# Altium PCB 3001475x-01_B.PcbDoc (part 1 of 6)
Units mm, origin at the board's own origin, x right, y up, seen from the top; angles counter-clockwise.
Board outline 335 x 91 mm, 12 copper layers (Top Layer, L2 GND, Layer 3, L4 GND, Layer 5, L6 PWR, L7 3V3, Layer 8, L9 GND, Layer 10, L11 GND, Bottom Layer), stack 1.59 mm thick; 339 components, 431 nets, 1732 pads, 1526 vias.
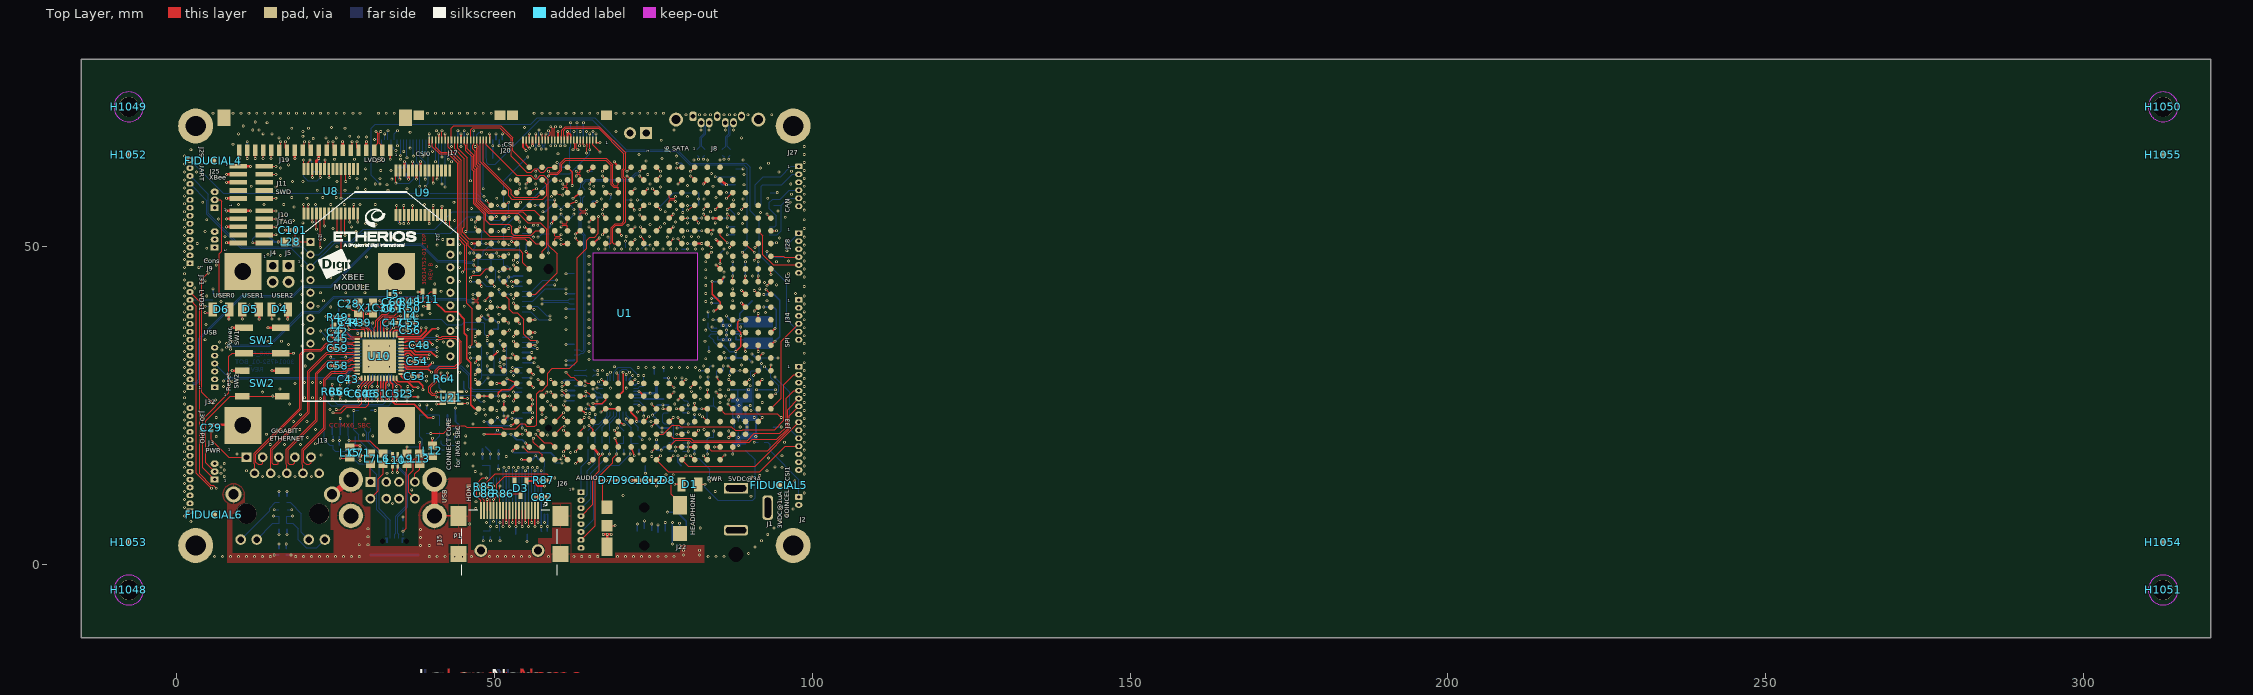
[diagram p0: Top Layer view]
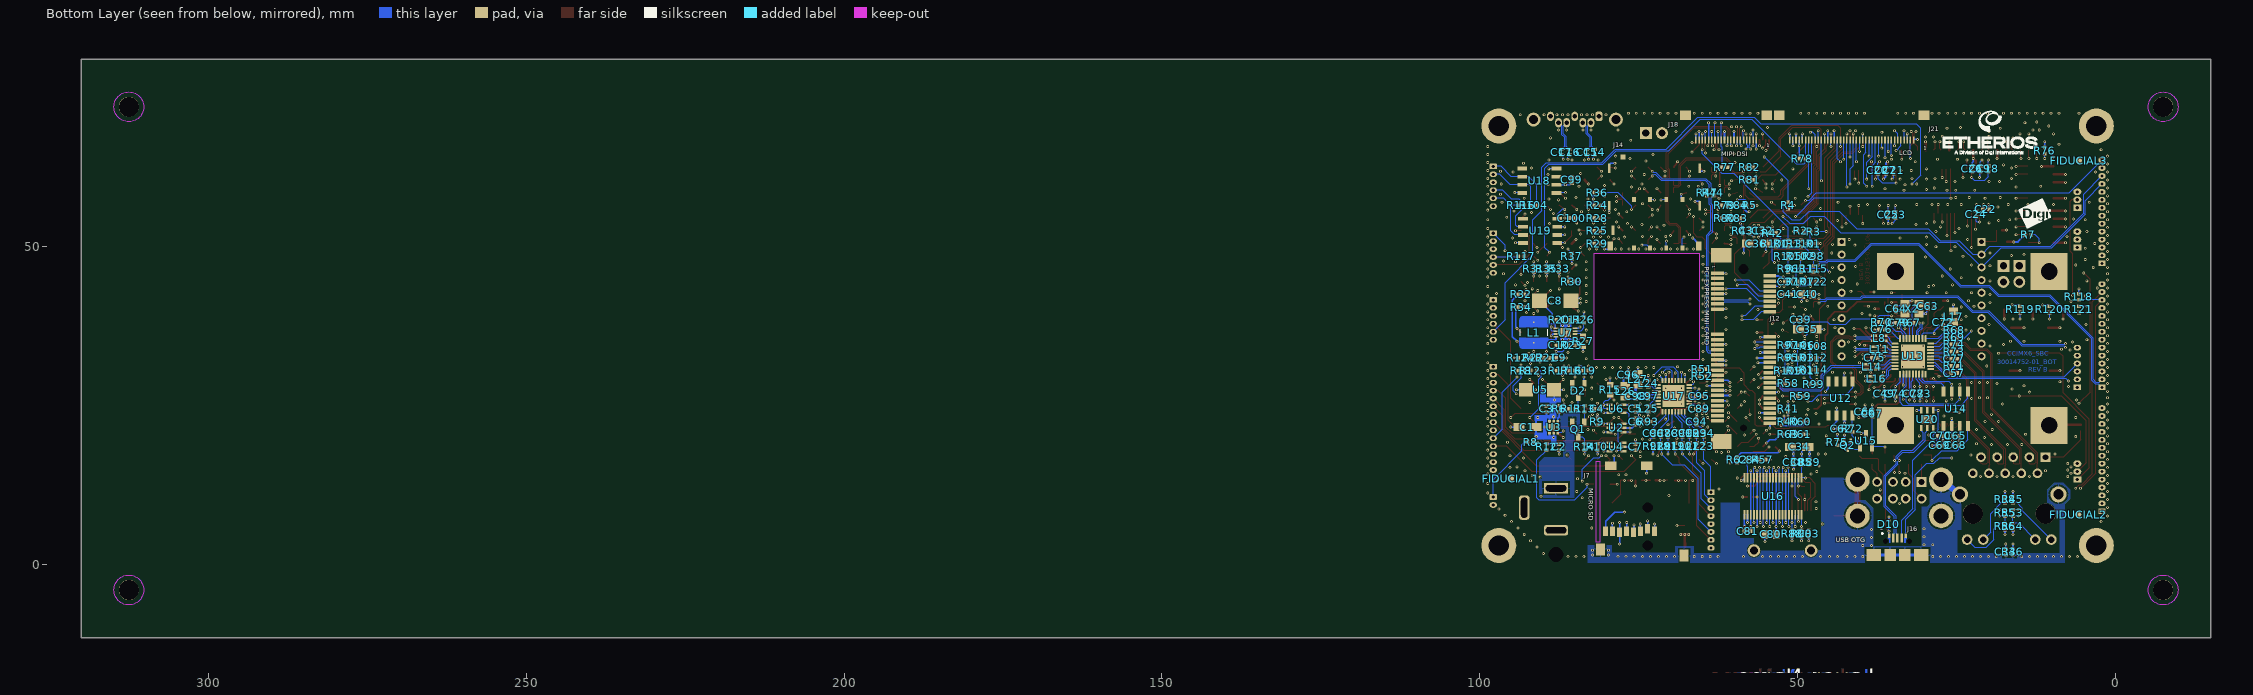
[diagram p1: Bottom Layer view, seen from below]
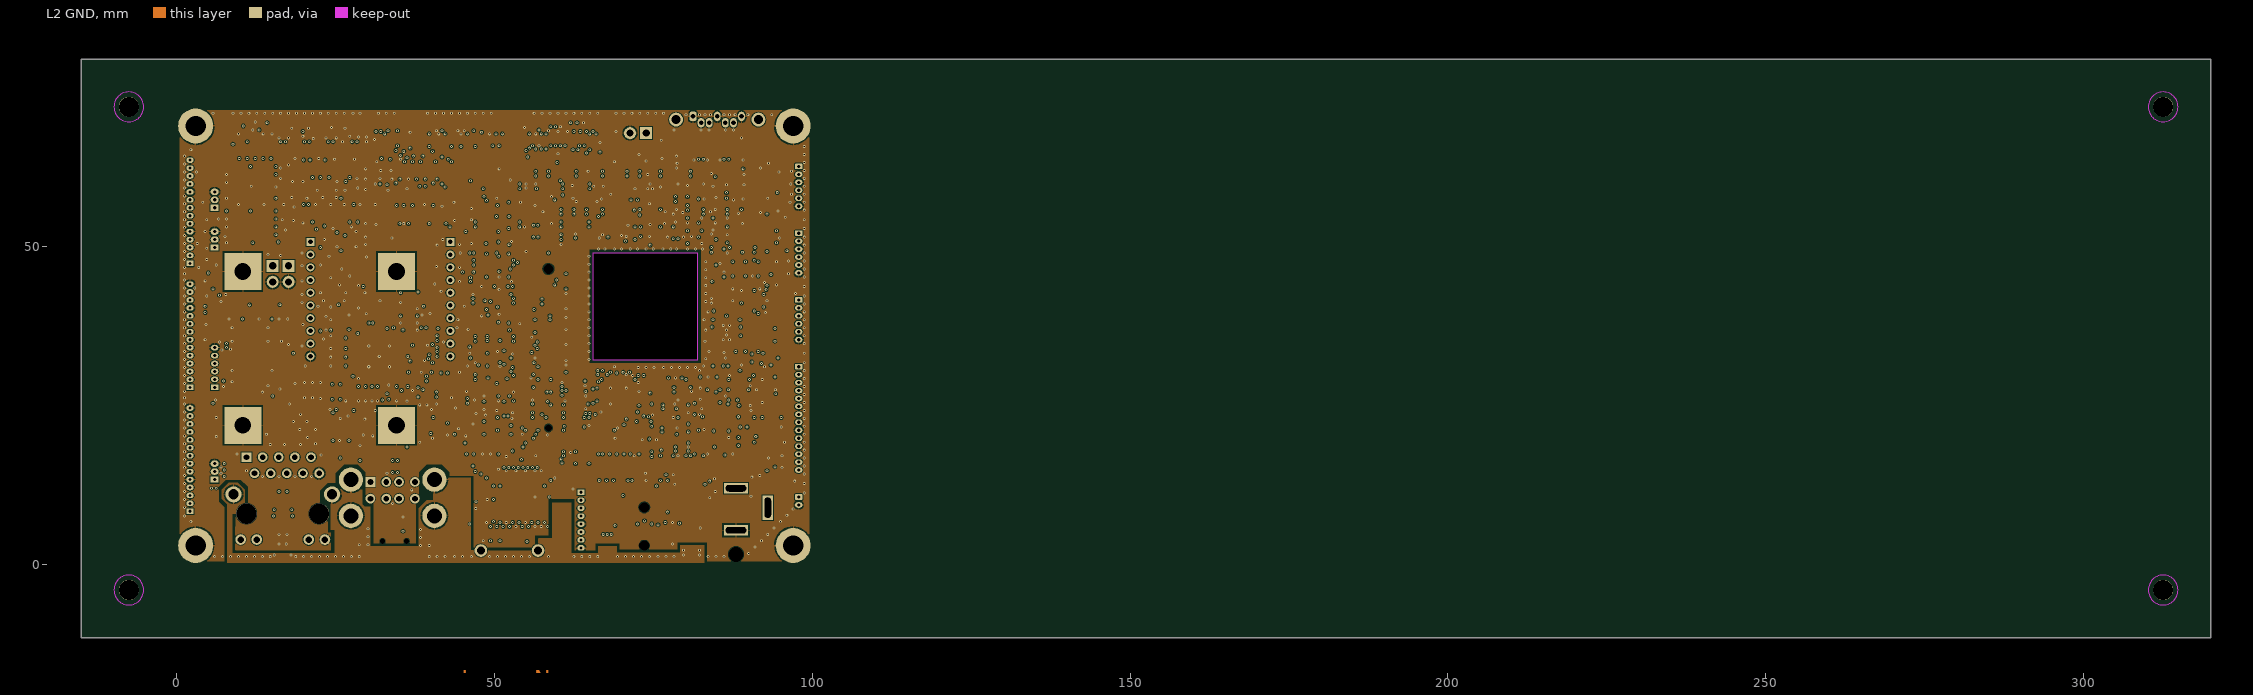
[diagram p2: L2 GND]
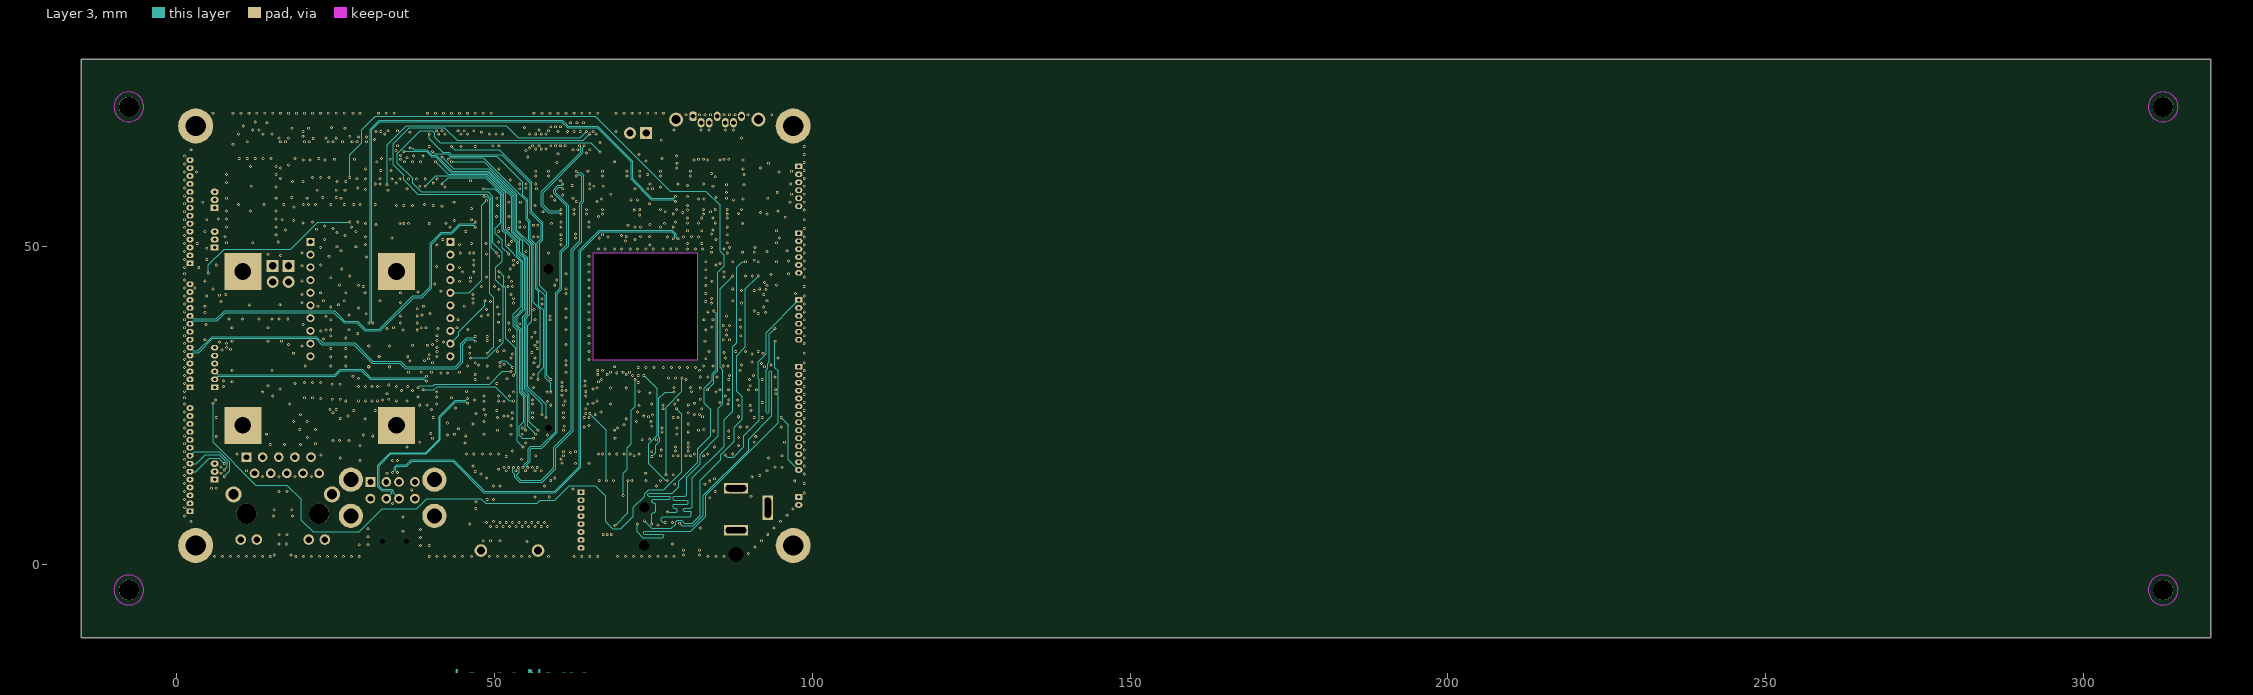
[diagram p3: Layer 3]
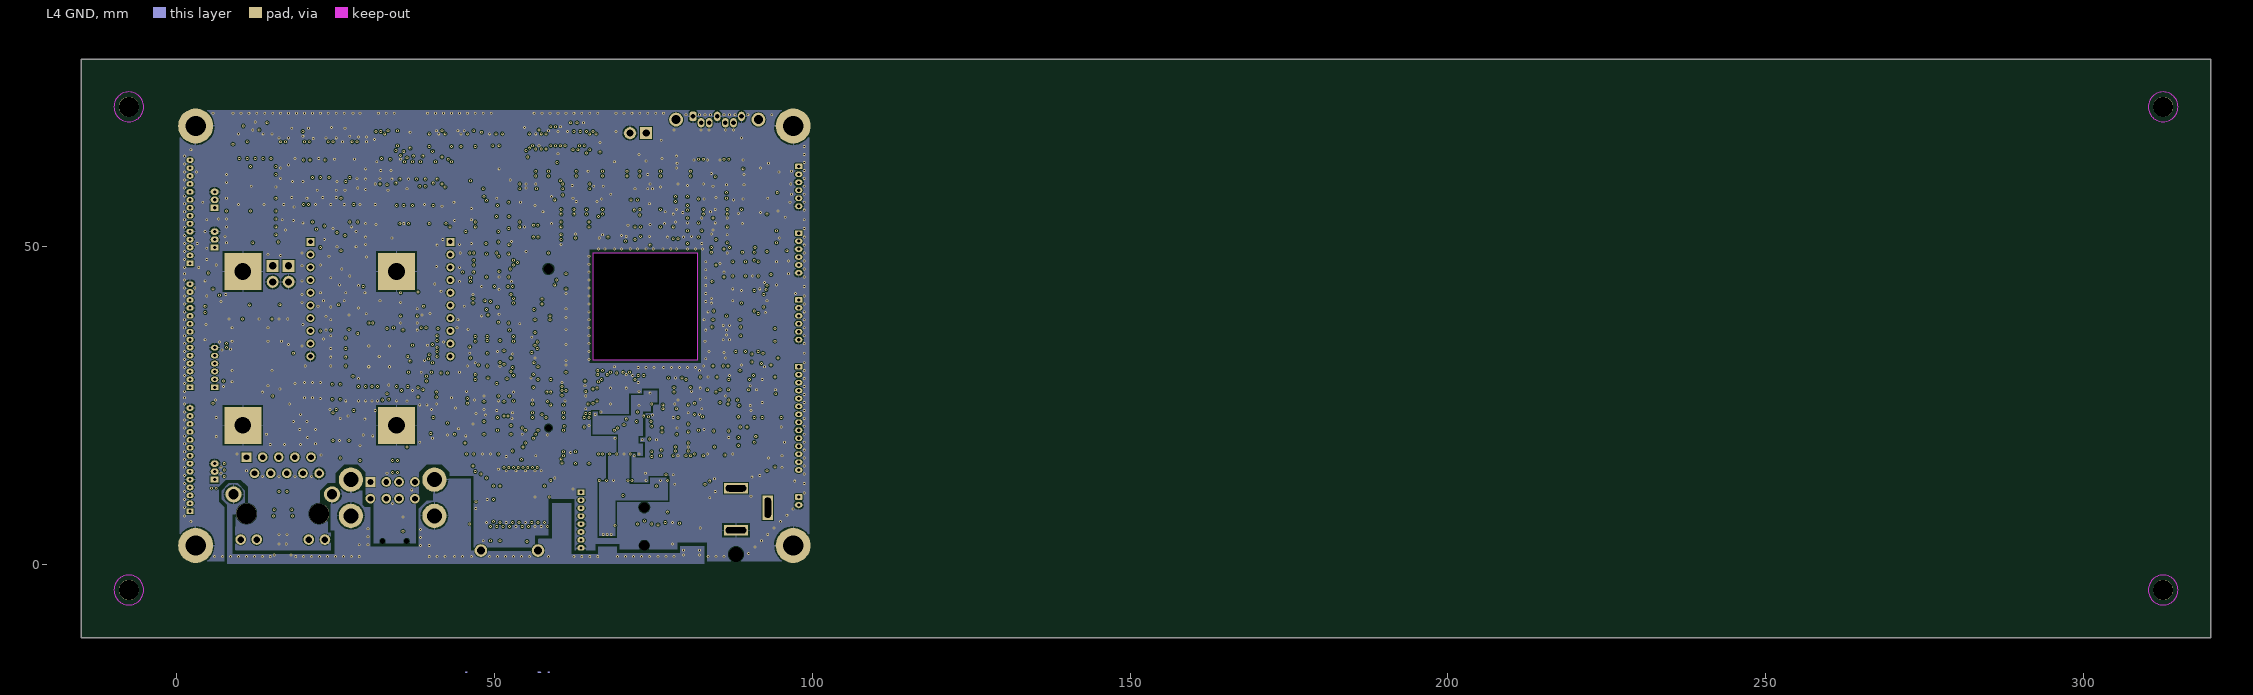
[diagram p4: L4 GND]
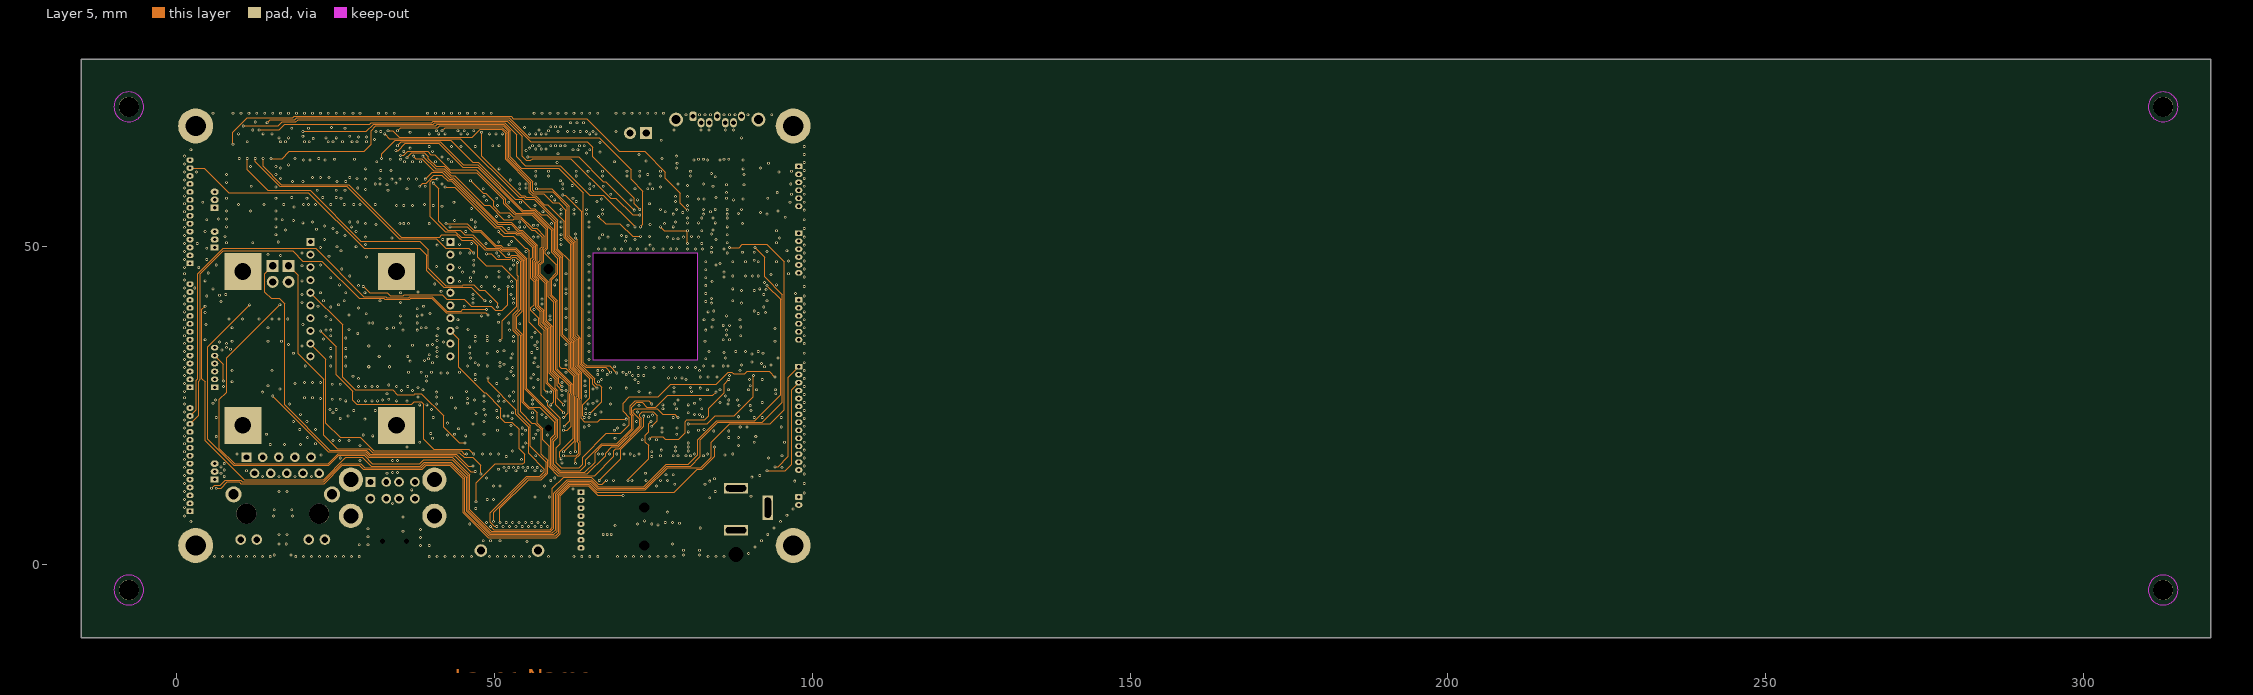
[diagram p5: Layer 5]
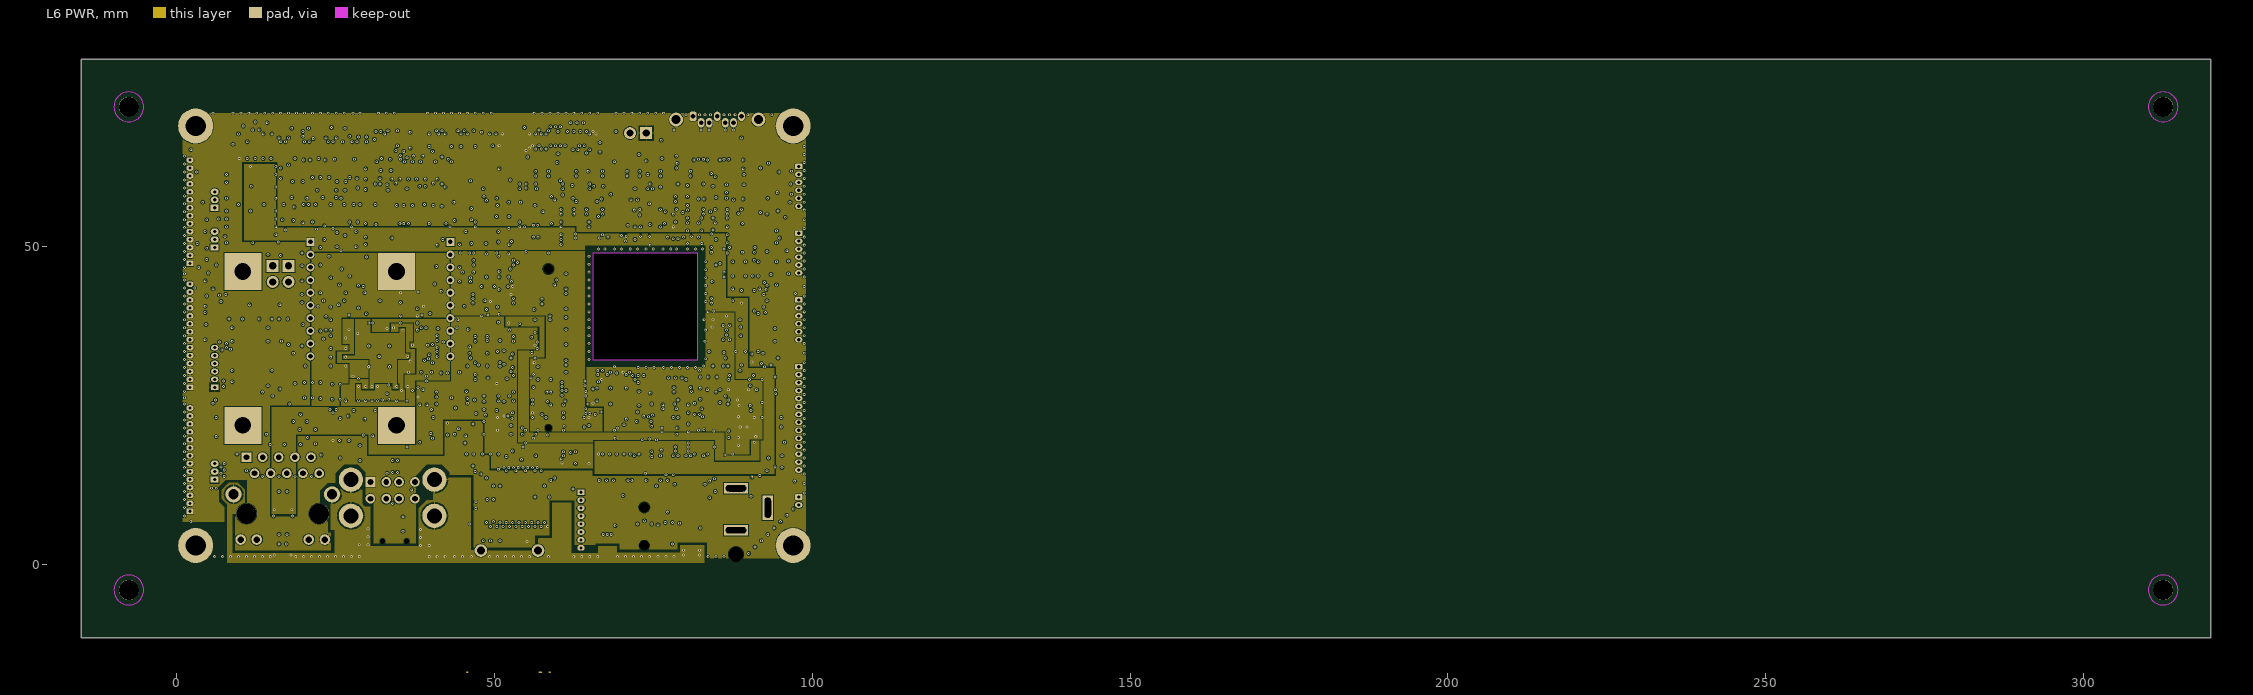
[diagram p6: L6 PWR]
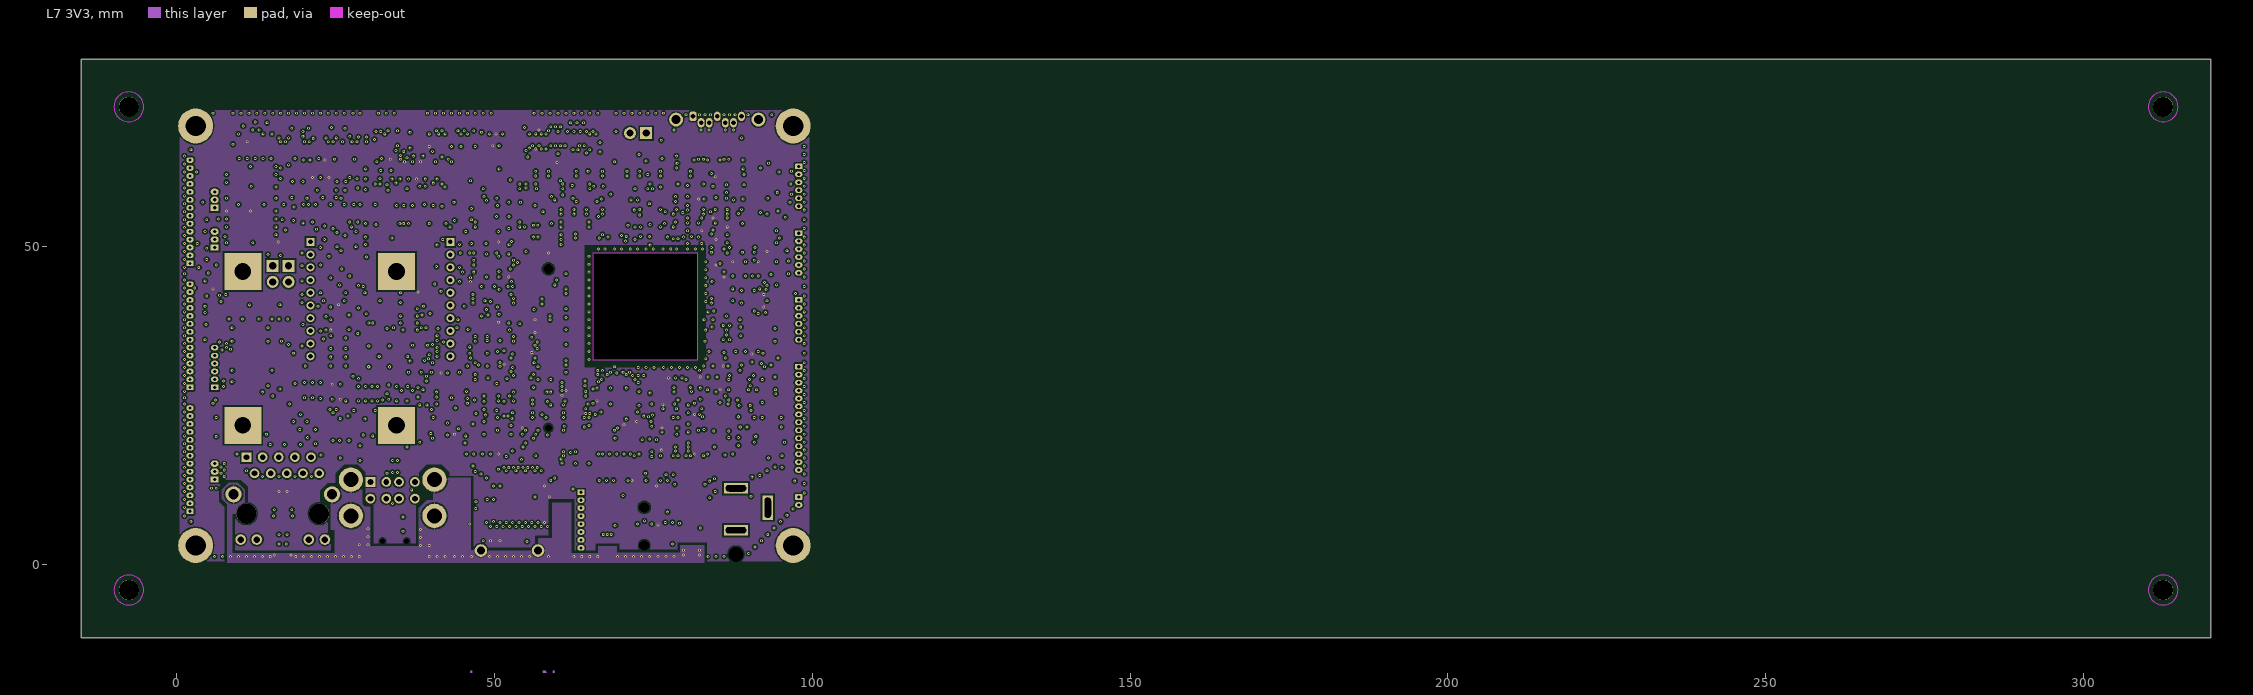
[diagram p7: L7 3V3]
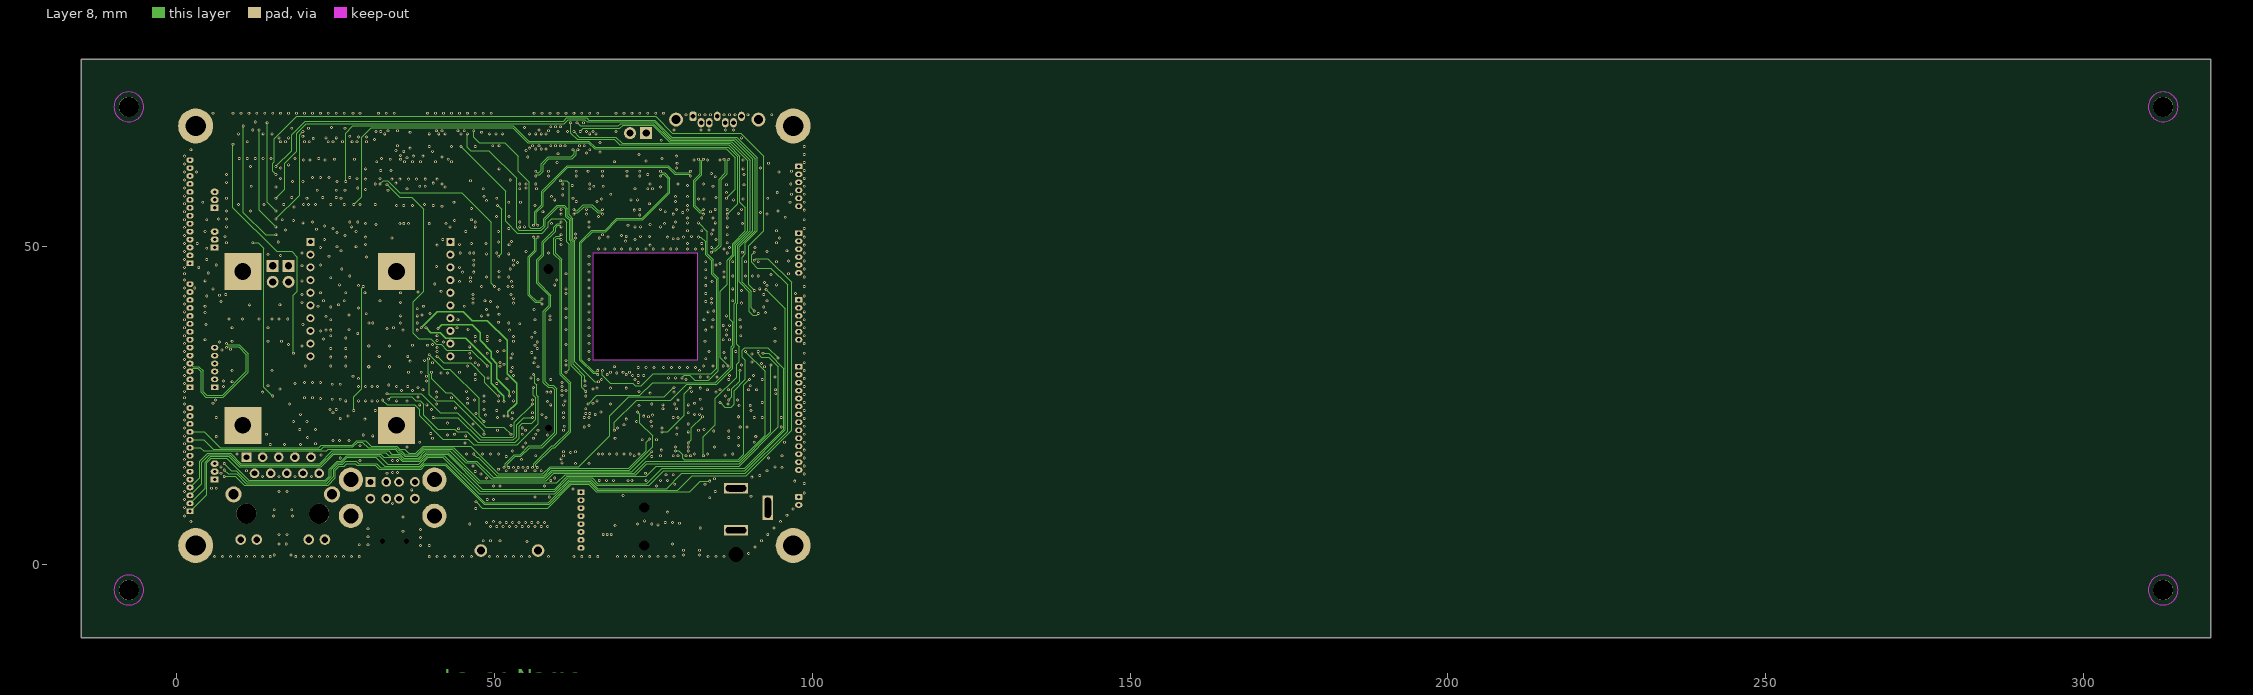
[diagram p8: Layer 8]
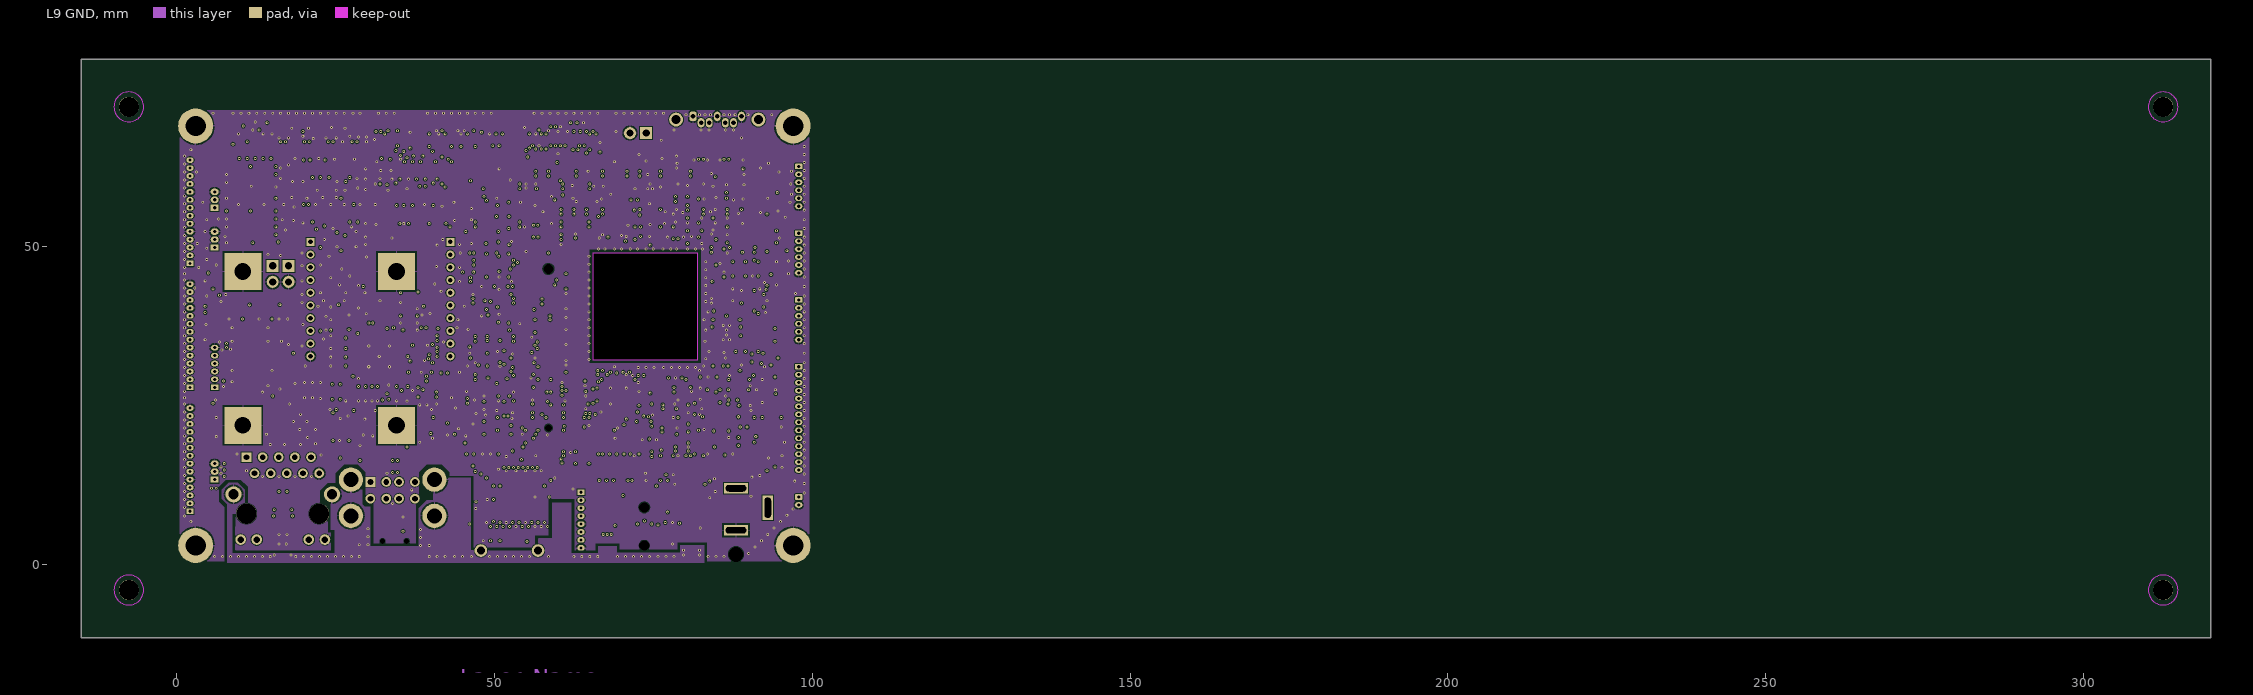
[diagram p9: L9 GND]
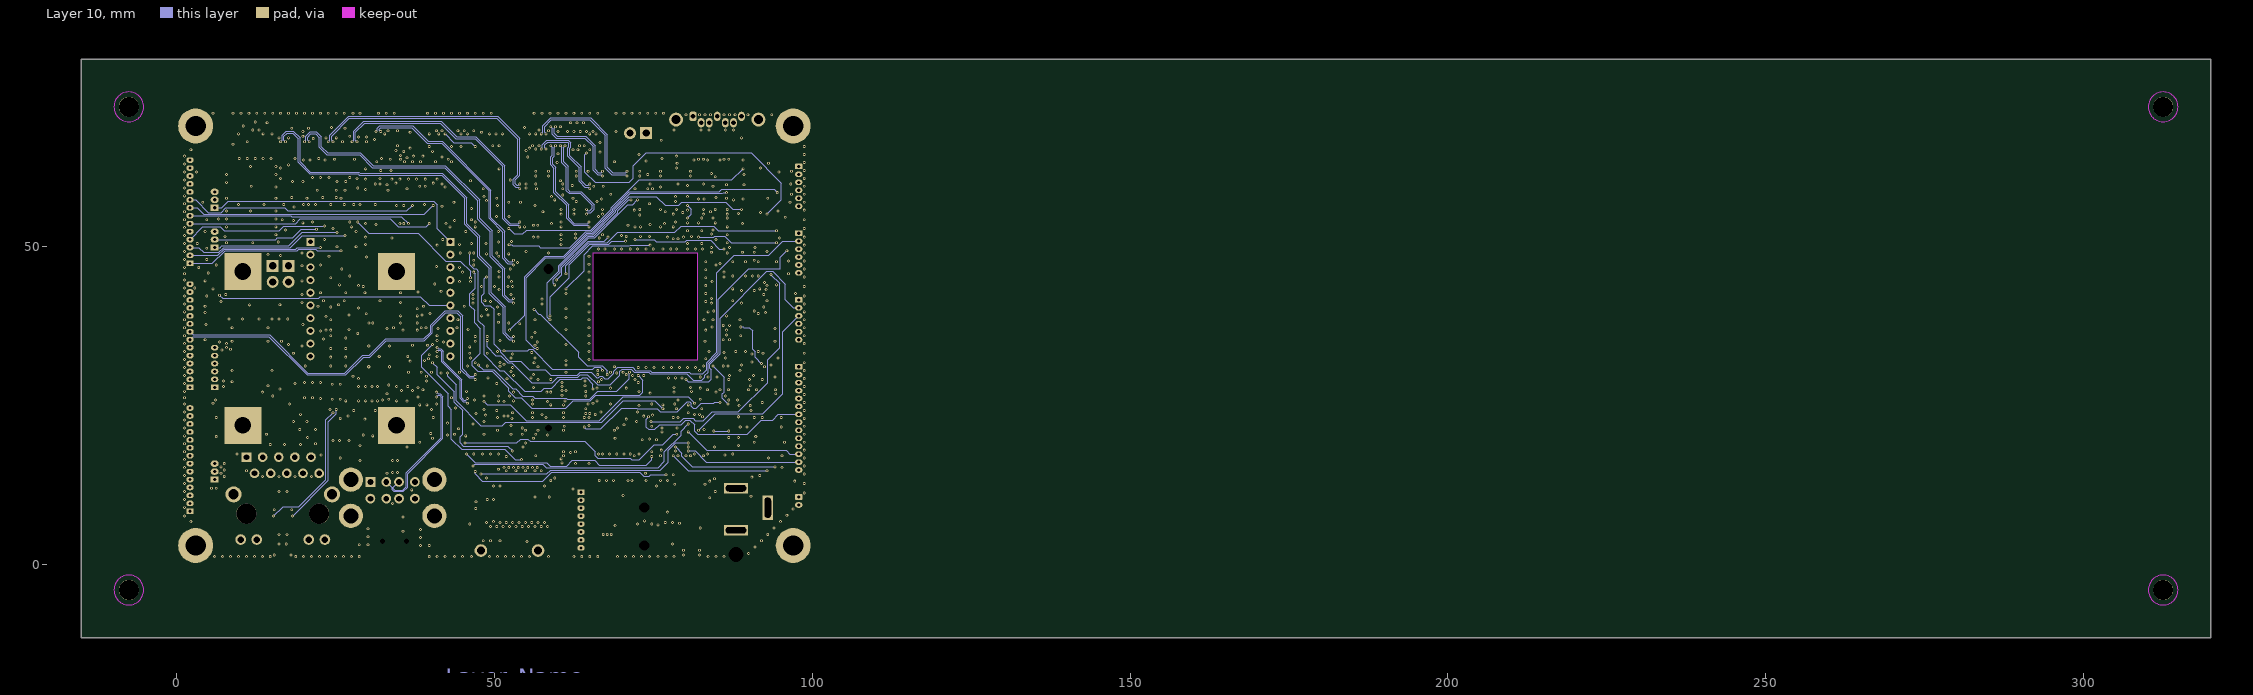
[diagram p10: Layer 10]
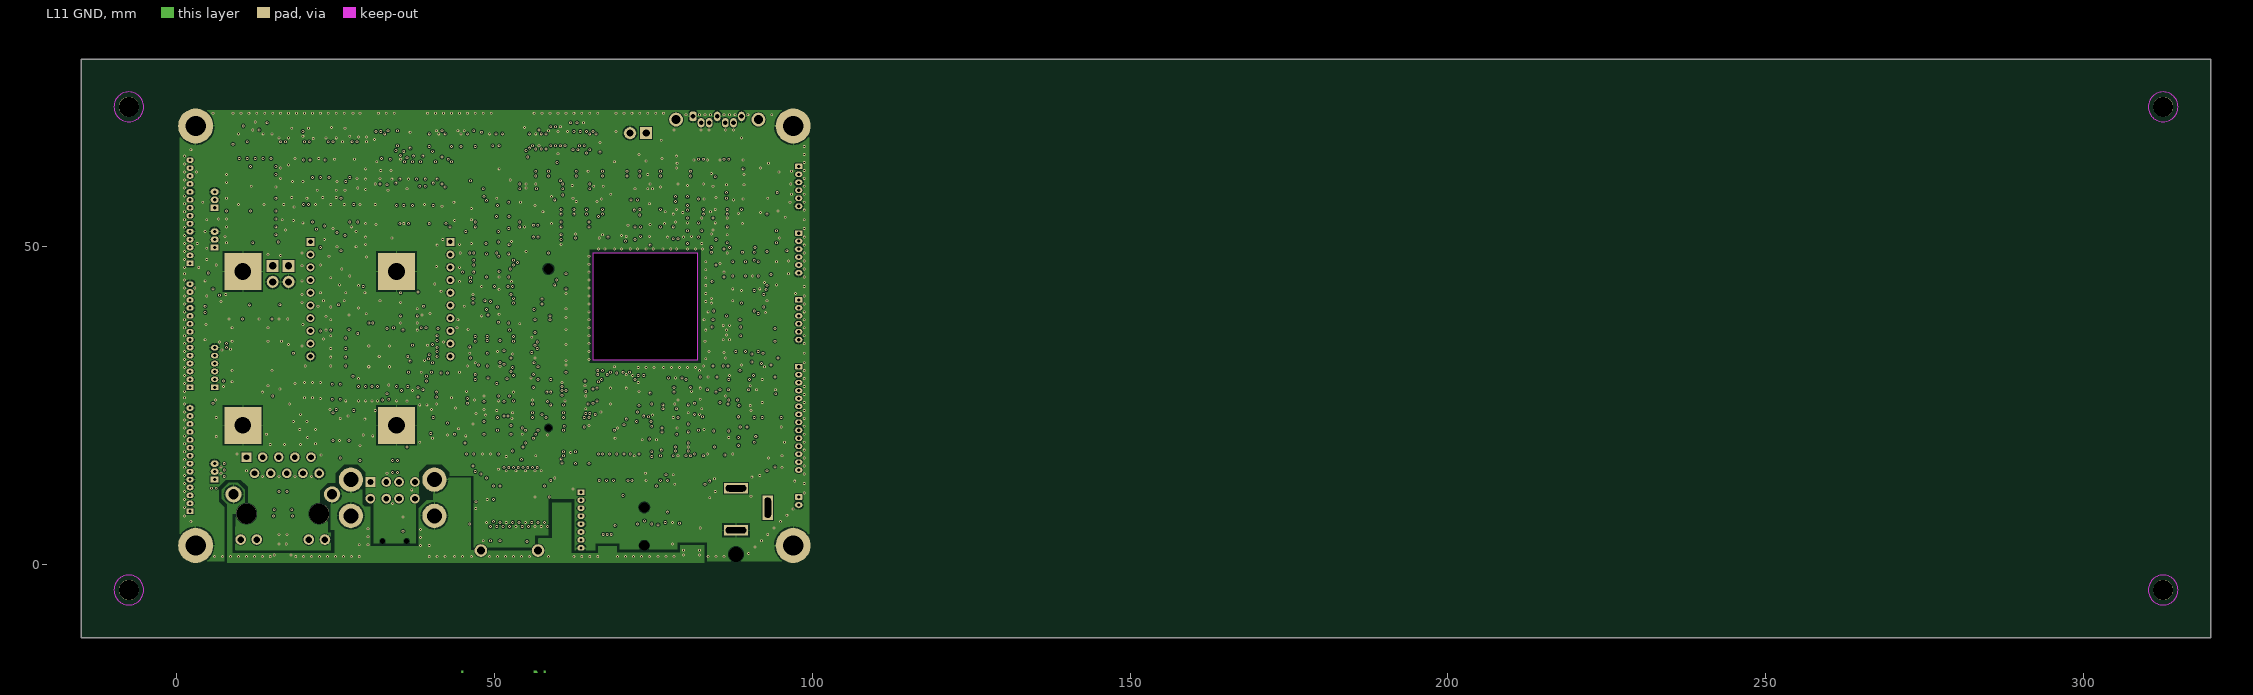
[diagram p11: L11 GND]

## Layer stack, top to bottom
Top Layer: signal copper 0.051
Dielectric: core 0.13, FR-4, Dk 4.02
L2 GND: signal copper 0.015
Dielectric: prepreg 0.102, FR-4, Dk 4.1
Layer 3: signal copper 0.015
Dielectric: core 0.142, FR-4, Dk 4.14
L4 GND: signal copper 0.015
Dielectric: prepreg 0.102, FR-4, Dk 4.1
Layer 5: signal copper 0.015
Dielectric: core 0.142, FR-4, Dk 4.14
L6 PWR: signal copper 0.015
Dielectric: prepreg 0.102, FR-4, Dk 4.1
L7 3V3: signal copper 0.015
Dielectric: core 0.142, FR-4, Dk 4.14
Layer 8: signal copper 0.015
Dielectric: prepreg 0.102, FR-4, Dk 4.1
L9 GND: signal copper 0.015
Dielectric: core 0.142, FR-4, Dk 4.14
Layer 10: signal copper 0.015
Dielectric: prepreg 0.102, FR-4, Dk 4.1
L11 GND: signal copper 0.015
Dielectric: core 0.13, FR-4, Dk 4.02
Bottom Layer: signal copper 0.051

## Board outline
-15,-11.5 -15,79.5 320,79.5 320,-11.5
cut-out: 65.5,32.25 82,32.25 82,49 65.5,49

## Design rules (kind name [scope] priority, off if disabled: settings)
AssemblyTestPointUsage [All] p1 off: valid=2
AssemblyTestpoint [All] p1 off: testpointundercomponent=TRUE minsize=1.016 maxsize=2.54 preferedsize=1.524 minholesize=0 maxholesize=1.016 preferedholesize=0.813 testpointgrid=0.025 usegrid=TRUE gridtolerance=0 allowsidetop=TRUE allowsidebottom=TRUE
Clearance "L7 Clearance" [(InNamedPolygon('Layer 7 3V3'))] p1: gap=0.25
Clearance "diff pairs to everything" [(InDifferentialPairClass('All Differential Pairs'))] p2 off: gap=0.1
Clearance "Global Clearance" [All] p3: gap=0.125
Clearance "2.5mm thru hole to SMT" [IsPad and inSMTComponent and onBottom vs IsThruPin And InThruComponent  And Not InComponent ('J22') And Not InComponent ('P1')] p4: gap=2.5
ComponentClearance [All] p1: gap=0.25 collisioncheckmode=3 verticalgap=0.25 showdistances=TRUE
DiffPairsRouting 85_Ohms [InDifferentialPairClass('85_Ohms')] p1: maxlimit=0.13 minlimit=0.12 mostfreqgap=0.125 midlayer1_mingap=0 midlayer1_maxgap=0 midlayer1_prefgap=0 midlayer2_mingap=0.125 midlayer2_maxgap=0.125 midlayer3_mingap=0 midlayer3_maxgap=0 midlayer3_prefgap=0 midlayer4_mingap=0.125 midlayer4_maxgap=0.125 midlayer5_mingap=0 midlayer5_maxgap=0 midlayer5_prefgap=0 midlayer6_mingap=0.125 midlayer6_maxgap=0.125 midlayer7_mingap=0 midlayer7_maxgap=0 midlayer7_prefgap=0 midlayer8_mingap=0 midlayer8_maxgap=0 midlayer8_prefgap=0 midlayer9_mingap=0 midlayer9_maxgap=0 midlayer9_prefgap=0 midlayer10_mingap=0 midlayer10_maxgap=0 midlayer10_prefgap=0 maxuncoupledlength=100
DiffPairsRouting 90_Ohms [InDifferentialPairClass('90_Ohms')] p2: maxlimit=0.125 minlimit=0.125 mostfreqgap=0.125 midlayer1_mingap=0 midlayer1_maxgap=0 midlayer1_prefgap=0 midlayer3_mingap=0 midlayer3_maxgap=0 midlayer3_prefgap=0 midlayer5_mingap=0 midlayer5_maxgap=0 midlayer5_prefgap=0 midlayer7_mingap=0 midlayer7_maxgap=0 midlayer7_prefgap=0 midlayer8_mingap=0 midlayer8_maxgap=0 midlayer8_prefgap=0 midlayer9_mingap=0 midlayer9_maxgap=0 midlayer9_prefgap=0 midlayer10_mingap=0 midlayer10_maxgap=0 midlayer10_prefgap=0 maxuncoupledlength=100
DiffPairsRouting 100_Ohms [InDifferentialPairClass('100_Ohms')] p3: maxlimit=0.2 minlimit=0.12 mostfreqgap=0.2 toplayer_maxgap=0.13 toplayer_prefgap=0.125 midlayer1_mingap=0 midlayer1_maxgap=0 midlayer1_prefgap=0 midlayer2_mingap=0.2 midlayer3_mingap=0 midlayer3_maxgap=0 midlayer3_prefgap=0 midlayer4_mingap=0.2 midlayer5_mingap=0 midlayer5_maxgap=0 midlayer5_prefgap=0 midlayer6_mingap=0.2 midlayer7_mingap=0 midlayer7_maxgap=0 midlayer7_prefgap=0 midlayer8_mingap=0 midlayer8_maxgap=0 midlayer8_prefgap=0 midlayer9_mingap=0 midlayer9_maxgap=0 midlayer9_prefgap=0 midlayer10_mingap=0 midlayer10_maxgap=0 midlayer10_prefgap=0 bottomlayer_maxgap=0.13 bottomlayer_prefgap=0.125 maxuncoupledlength=100
FabricationTestPointUsage TestPointUsage [All] p1 off: valid=2 allowmultiple=FALSE
FabricationTestpoint Testpoint [All] p1 off: side=3 testpointundercomponent=TRUE minsize=1.016 maxsize=2.54 preferedsize=1.524 minholesize=0 maxholesize=1.016 preferedholesize=0.813 testpointgrid=0.025 allowsidetop=TRUE allowsidebottom=TRUE usegrid=TRUE gridtolerance=0
HoleSize [All] p1: absolutevalues=TRUE maxlimit=6 minlimit=0.15 maxpercent=80.000 minpercent=20.000
HoleToHoleClearance [All] p1: gap=0.25 allowstackedmicrovias=TRUE
MinimumAnnularRing "No Plating" [Not PadIsPlated] p1: minimumring=0
MinimumAnnularRing [All] p2: minimumring=0.1
MinimumSolderMaskSliver [All] p1: minsoldermaskwidth=0.1
PlaneClearance "3V3 PlaneClearance" [(InNamedPolygon('Layer 7 3V3'))] p1: clearance=0.25
PlaneClearance [All] p2: clearance=0.25
PlaneConnect [All] p1: planeconnectstyle=Relief reliefexpansion=0.2 reliefentries=4 reliefconductorwidth=0.2 reliefairgap=0.2
PlaneConnect "Via_ Direct_Connect_to_Plane" [IsVia] p2: planeconnectstyle=Direct reliefexpansion=0.508 reliefentries=4 reliefconductorwidth=0.254 reliefairgap=0.254
PolygonConnect "Polygon To Via" [IsVia] p1: connectstyle=Direct reliefconductorwidth=0.254 reliefentries=4 polygonreliefangle="90 Angle" airgapwidth=0.254
PolygonConnect [All] p2: connectstyle=Relief reliefconductorwidth=0.2 reliefentries=4 polygonreliefangle="90 Angle" airgapwidth=0.25
RoutingCorners [All] p1: cornerstyle=45-Degree minsetback=2.5 maxsetback=2.5
RoutingLayers RoutingLayers_Power [InNetClass('Power')] p1: top layer_v5=TRUE mid layer 1_v5=TRUE mid layer 2_v5=TRUE mid layer 3_v5=TRUE mid layer 4_v5=TRUE mid layer 5_v5=TRUE mid layer 6_v5=TRUE mid layer 7_v5=FALSE mid layer 8_v5=FALSE mid layer 9_v5=FALSE mid layer 10_v5=FALSE bottom layer_v5=TRUE
RoutingLayers RoutingLayers_50_Ohms [InNetClass('50_Ohm')] p2: top layer_v5=TRUE mid layer 1_v5=FALSE mid layer 2_v5=TRUE mid layer 3_v5=FALSE mid layer 4_v5=TRUE mid layer 5_v5=FALSE mid layer 6_v5=TRUE mid layer 7_v5=FALSE mid layer 8_v5=FALSE mid layer 9_v5=FALSE mid layer 10_v5=FALSE bottom layer_v5=TRUE
RoutingLayers RoutingLayers_GND [InNetClass('GND')] p3: top layer_v5=TRUE mid layer 1_v5=FALSE mid layer 2_v5=FALSE mid layer 3_v5=FALSE mid layer 4_v5=FALSE mid layer 5_v5=FALSE mid layer 6_v5=FALSE mid layer 7_v5=TRUE mid layer 8_v5=TRUE mid layer 9_v5=TRUE mid layer 10_v5=TRUE bottom layer_v5=TRUE
RoutingLayers "RoutingLayers_100_Ohm Diff Pairs" [InDifferentialPairClass ('100_Ohms')] p4: top layer_v5=TRUE mid layer 1_v5=FALSE mid layer 2_v5=TRUE mid layer 3_v5=FALSE mid layer 4_v5=TRUE mid layer 5_v5=FALSE mid layer 6_v5=TRUE mid layer 7_v5=FALSE mid layer 8_v5=FALSE mid layer 9_v5=FALSE mid layer 10_v5=FALSE bottom layer_v5=TRUE
RoutingLayers "RoutingLayers_90_Ohm Diff Pairs" [InDifferentialPairClass ('90_Ohms')] p5: top layer_v5=TRUE mid layer 1_v5=FALSE mid layer 2_v5=TRUE mid layer 3_v5=FALSE mid layer 4_v5=TRUE mid layer 5_v5=FALSE mid layer 6_v5=TRUE mid layer 7_v5=FALSE mid layer 8_v5=FALSE mid layer 9_v5=FALSE mid layer 10_v5=FALSE bottom layer_v5=TRUE
RoutingLayers "RoutingLayers_85_Ohm Diff Pairs" [InDifferentialPairClass ('85_Ohms')] p6: top layer_v5=TRUE mid layer 1_v5=FALSE mid layer 2_v5=TRUE mid layer 3_v5=FALSE mid layer 4_v5=TRUE mid layer 5_v5=FALSE mid layer 6_v5=TRUE mid layer 7_v5=FALSE mid layer 8_v5=FALSE mid layer 9_v5=FALSE mid layer 10_v5=FALSE bottom layer_v5=TRUE
RoutingLayers [All] p7: top layer_v5=TRUE mid layer 1_v5=TRUE mid layer 2_v5=TRUE mid layer 3_v5=TRUE mid layer 4_v5=TRUE mid layer 5_v5=TRUE mid layer 6_v5=TRUE mid layer 7_v5=TRUE mid layer 8_v5=TRUE mid layer 9_v5=TRUE mid layer 10_v5=TRUE bottom layer_v5=TRUE
RoutingVias [All] p1: holewidth=0.2 width=0.45 viastyle="Through Hole" minholewidth=0.15 minwidth=0.4 maxholewidth=0.3 maxwidth=1.25
SilkToSilkClearance [All] p1: silktosilkclearance=0.125
SilkscreenOverComponentPads [IsPad] p1: minsilkscreentomaskgap=0.125
SolderMaskExpansion "Feedthru Via" [IsVia] p1: expansion=-0.025
SolderMaskExpansion "SolderMaskExpansion_FCI Headers" [HasFootprint('FCI_68002-102HLF')] p2 off: expansion=2.5
SolderMaskExpansion SolderMaskExpansion_Xbee [HasFootprint('SAMTEC_MMS-110-01-L-SV')] p3 off: expansion=2.5
SolderMaskExpansion SolderMaskExpansion_USB [HasFootprint('KYCON_KUSBX-AS2N')] p4 off: expansion=2.5
SolderMaskExpansion SolderMaskExpansion_Ethernet [HasFootprint('BELFUSE_61001-F')] p5 off: expansion=2.5
SolderMaskExpansion [All] p6: expansion=0.05
Width "Width 100_Ohms" [InDifferentialPairClass('100_Ohms')] p1: maxlimit=0.122 minlimit=0.101 preferedwidth=0.101 toplayer_minwidth=0.122 toplayer_prefwidth=0.122 midlayer1_minwidth=0 midlayer1_maxwidth=0 midlayer1_prefwidth=0 midlayer2_maxwidth=0.101 midlayer3_minwidth=0 midlayer3_maxwidth=0 midlayer3_prefwidth=0 midlayer4_maxwidth=0.101 midlayer5_minwidth=0 midlayer5_maxwidth=0 midlayer5_prefwidth=0 midlayer6_maxwidth=0.101 midlayer7_minwidth=0 midlayer7_maxwidth=0 midlayer7_prefwidth=0 midlayer8_minwidth=0 midlayer8_maxwidth=0 midlayer8_prefwidth=0 midlayer9_minwidth=0 midlayer9_maxwidth=0 midlayer9_prefwidth=0 midlayer10_minwidth=0 midlayer10_maxwidth=0 midlayer10_prefwidth=0 bottomlayer_minwidth=0.122 bottomlayer_prefwidth=0.122 minimp=50.000000 maximp=50.000000 favimp=50.000000 checkconnectedcopper=TRUE
Width "Width 90_Ohms" [InDifferentialPairClass('90_Ohms')] p2: maxlimit=0.155 minlimit=0.103 preferedwidth=0.103 toplayer_minwidth=0.155 toplayer_prefwidth=0.155 midlayer1_minwidth=0 midlayer1_maxwidth=0 midlayer1_prefwidth=0 midlayer2_maxwidth=0.103 midlayer3_minwidth=0 midlayer3_maxwidth=0 midlayer3_prefwidth=0 midlayer4_maxwidth=0.103 midlayer5_minwidth=0 midlayer5_maxwidth=0 midlayer5_prefwidth=0 midlayer6_maxwidth=0.103 midlayer7_minwidth=0 midlayer7_maxwidth=0 midlayer7_prefwidth=0 midlayer8_minwidth=0 midlayer8_maxwidth=0 midlayer8_prefwidth=0 midlayer9_minwidth=0 midlayer9_maxwidth=0 midlayer9_prefwidth=0 midlayer10_minwidth=0 midlayer10_maxwidth=0 midlayer10_prefwidth=0 bottomlayer_minwidth=0.155 bottomlayer_prefwidth=0.155 minimp=50.000000 maximp=50.000000 favimp=50.000000 checkconnectedcopper=TRUE
Width "Width 85_Ohms" [InDifferentialPairClass('85_Ohms')] p3: maxlimit=0.175 minlimit=0.119 preferedwidth=0.119 toplayer_minwidth=0.175 toplayer_prefwidth=0.175 midlayer1_minwidth=0 midlayer1_maxwidth=0 midlayer1_prefwidth=0 midlayer2_maxwidth=0.119 midlayer3_minwidth=0 midlayer3_maxwidth=0 midlayer3_prefwidth=0 midlayer4_maxwidth=0.119 midlayer5_minwidth=0 midlayer5_maxwidth=0 midlayer5_prefwidth=0 midlayer6_maxwidth=0.119 midlayer7_minwidth=0 midlayer7_maxwidth=0 midlayer7_prefwidth=0 midlayer8_minwidth=0 midlayer8_maxwidth=0 midlayer8_prefwidth=0 midlayer9_minwidth=0 midlayer9_maxwidth=0 midlayer9_prefwidth=0 midlayer10_minwidth=0 midlayer10_maxwidth=0 midlayer10_prefwidth=0 bottomlayer_minwidth=0.175 bottomlayer_prefwidth=0.175 minimp=50.000000 maximp=50.000000 favimp=50.000000 checkconnectedcopper=TRUE
Width "Width 50_Ohms" [InNetClass('50_Ohms')] p4: maxlimit=0.2 minlimit=0.104 preferedwidth=0.104 toplayer_minwidth=0.2 toplayer_prefwidth=0.2 midlayer1_minwidth=0 midlayer1_maxwidth=0 midlayer1_prefwidth=0 midlayer2_maxwidth=0.104 midlayer3_minwidth=0 midlayer3_maxwidth=0 midlayer3_prefwidth=0 midlayer4_maxwidth=0.104 midlayer5_minwidth=0 midlayer5_maxwidth=0 midlayer5_prefwidth=0 midlayer6_maxwidth=0.104 midlayer7_minwidth=0 midlayer7_maxwidth=0 midlayer7_prefwidth=0 midlayer8_minwidth=0 midlayer8_maxwidth=0 midlayer8_prefwidth=0 midlayer9_minwidth=0 midlayer9_maxwidth=0 midlayer9_prefwidth=0 midlayer10_minwidth=0 midlayer10_maxwidth=0 midlayer10_prefwidth=0 bottomlayer_minwidth=0.2 bottomlayer_prefwidth=0.2 minimp=50.000000 maximp=50.000000 favimp=50.000000
Width "Width Power" [InNetClass('Power')] p5: maxlimit=1 minlimit=0.125 preferedwidth=0.25
Width "Width GND" [InNetClass('GND')] p6: maxlimit=1 minlimit=0.125 preferedwidth=0.3
Width [All] p7: maxlimit=0.5 minlimit=0.1 preferedwidth=0.125
13 further rules are at their usual default settings.

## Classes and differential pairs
net class Clocks: AUD_CLK CSI0_MCLK CSI0_PIXCLK CSI1_MCLK CSI1_PIXCLK DISP0_CLK MCA_SWD_CLK NetJ7_5 NetR48_2 PCIE_UIM_CLK RGMII_REF_CLK SD2_CLK SPI1_CLK
component class Connectors: J1 J2 J3 J4 J5 J6 J7 J8 J9 J10 J11 J12 J13 J14 J15 J16 J17 J18 J19 J20 J21 J22 J23 J24 J25 J26 J27 J28 J29 J30 J31 J32 J33 J34 P1
differential pair class 85_Ohms: CLK1 PCIE_RX PCIE_TX PCIECLK PCIERX PCIETX
differential pair class 90_Ohms: OTGD USB_OTG_D USBH1_D USBH2_D USBH3_D USBH4_D USBH_D
differential pair class 100_Ohms: CSI_CLK0 CSI_D0 CSI_D1 CSI_D2 CSI_D3 CSID2 CSID3 DSI_CLK0 DSI_D0 DSI_D1 ETH_TXRXA ETH_TXRXB ETH_TXRXC ETH_TXRXD HDMI_CLK HDMI_D0 HDMI_D1 HDMI_D2 LVDS0_CLK LVDS0_TX0 LVDS0_TX1 LVDS0_TX2 LVDS0_TX3 LVDS1_CLK LVDS1_TX0 LVDS1_TX1 LVDS1_TX2 LVDS1_TX3 SATA_RX SATA_TX SATARX SATATX
component class "11 - Expansion Connectors, User LEDs": D4 D5 D6 J26 J27 J28 J29 J30 J31 J32 J33 J34 R117 R118 R119 R120 R121 R122
component class "10 - CAN, I2C, XBee": C99 C100 C101 J23 J24 J25 L28 R95 R96 R97 R98 R99 R100 R101 R102 R103 R104 R105 R106 R107 R108 R109 R110 R111 R112 R113 R114 R115 R116 U18 U19
component class "09 - Audio": C87 C88 C89 C90 C91 C92 C93 C94 C95 C96 C97 C98 D7 D8 D9 J22 L18 L19 L20 L21 L22 L23 L24 L25 L26 L27 R91 R92 R93 R94 U17
component class "08 - Displays, HDMI, Cameras": C80 C81 C82 C83 C84 C85 C86 D3 J17 J18 J19 J20 J21 P1 R76 R77 R78 R79 R80 R81 R82 R83 R84 R85 R86 R87 R88 R89 R90 U16
component class "07 - USB OTG, USB HUB, USB Host": C62 C63 C64 C65 C66 C67 C68 C69 C70 C71 C72 C73 C74 C75 C76 C77 C78 C79 D10 J15 J16 L6 L7 L8 L9 L10 L11 L12 L13 L14 L15 L16 L17 Q2 R64 R65 R66 R67 R68 R69 R70 R71 R72 R73 R74 R75 U12 U13 U14 U15 U20 U21 X2
component class "06 - Gigabit Ethernet, Mini PCIe, microSIM": C28 C29 C30 C31 C32 C33 C34 C35 C36 C37 C38 C39 C40 C41 C42 C43 C44 C45 C46 C47 C48 C49 C50 C51 C52 C53 C54 C55 C56 C57 C58 C59 C60 C61 J12 J13 J14 L2 L3 L4 L5 R38 R39 R40 R41 R42 R43 R44 R45 R46 R47 R48 R49 R50 R51 R52 R53 R54 R55 R56 R57 R58 R59 R60 R61 R62 R63 U10 U11 X1
component class "05 - JTAG, SWD, Console, UART": C18 C19 C20 C21 C22 C23 C24 C25 C26 C27 J9 J10 J11 R36 R37 U8 U9
component class "03 - Power, Battery charger, boot": C1 C2 C3 C4 C5 C6 C7 C8 C9 C10 C11 D1 D2 J1 J2 J3 J4 J5 L1 Q1 R6 R7 R8 R9 R10 R11 R12 R13 R14 R15 R16 R17 R18 R19 R20 R21 R22 R23 R24 R25 R26 R27 R28 R29 R123 R124 SW1 SW2 U2 U3 U4 U5 U6 U7
component class "02 - CCIMX6 Module": R1 R2 R3 R4 R5 U1
component class "04 - SATA, microSD": C12 C13 C14 C15 C16 C17 J6 J7 J8 R30 R31 R32 R33 R34 R35
component class IC's: Q1 Q2 SW1 U1 U2 U3 U4 U5 U6 U7 U8 U9 U10 U11 U12 U13 U14 U15 U16 U17 U18 U19 X1 X2
net class Power: 3V3 5V NetC42_2 NetC46_2 NetC50_2 NetC72_2 RGMII_1V2 VCC_LICELL VIN VLDO3_MCA VLDO4_2V5 VLDO6_1V5 VSYS
net class GND: AGND GND SHLD
net class 50_Ohm: NetJ7_5 RGMII_RD0 RGMII_RD1 RGMII_RD2 RGMII_RD3 RGMII_REF_CLK RGMII_RX_CTL RGMII_RXC RGMII_TD0 RGMII_TD1 RGMII_TD2 RGMII_TD3 RGMII_TX_CTL RGMII_TXC SD2_CLK SD2_CMD SD2_DAT0 SD2_DAT1 SD2_DAT2 SD2_DAT3
differential pair USBH2_D: +USBH2_D_P -USBH2_D_N
differential pair USBH3_D: +USBH3_D_P -USBH3_D_N
differential pair USBH4_D: +USBH4_D_P -USBH4_D_N
differential pair OTGD: +OTGD_P -OTGD_N
differential pair USBH_D: +USBH_D_P -USBH_D_N
differential pair USBH1_D: +USBH1_D_P -USBH1_D_N
differential pair USB_OTG_D: +USB_OTG_D_P -USB_OTG_D_N
differential pair SATATX: +SATATX_P -SATATX_N
differential pair SATARX: +SATARX_P -SATARX_N
differential pair SATA_TX: +SATA_TX_P -SATA_TX_N
differential pair SATA_RX: +SATA_RX_P -SATA_RX_N
differential pair PCIETX: +PCIETX_P -PCIETX_N
differential pair PCIERX: +PCIERX_P -PCIERX_N
differential pair PCIECLK: +PCIECLK_P -PCIECLK_N
differential pair PCIE_TX: +PCIE_TX_P -PCIE_TX_N
differential pair PCIE_RX: +PCIE_RX_P -PCIE_RX_N
differential pair LVDS1_TX3: +LVDS1_TX3_P -LVDS1_TX3_N
differential pair LVDS1_TX2: +LVDS1_TX2_P -LVDS1_TX2_N
differential pair LVDS1_TX1: +LVDS1_TX1_P -LVDS1_TX1_N
differential pair LVDS1_TX0: +LVDS1_TX0_P -LVDS1_TX0_N
differential pair LVDS1_CLK: +LVDS1_CLK_P -LVDS1_CLK_N
differential pair LVDS0_TX3: +LVDS0_TX3_P -LVDS0_TX3_N
differential pair LVDS0_TX2: +LVDS0_TX2_P -LVDS0_TX2_N
differential pair LVDS0_TX1: +LVDS0_TX1_P -LVDS0_TX1_N
differential pair LVDS0_TX0: +LVDS0_TX0_P -LVDS0_TX0_N
differential pair LVDS0_CLK: +LVDS0_CLK_P -LVDS0_CLK_N
differential pair HDMI_D2: +HDMI_D2_P -HDMI_D2_N
differential pair HDMI_D1: +HDMI_D1_P -HDMI_D1_N
differential pair HDMI_D0: +HDMI_D0_P -HDMI_D0_N
differential pair HDMI_CLK: +HDMI_CLK_P -HDMI_CLK_N
differential pair ETH_TXRXD: +ETH_TXRXD_P -ETH_TXRXD_N
differential pair ETH_TXRXC: +ETH_TXRXC_P -ETH_TXRXC_N
differential pair ETH_TXRXB: +ETH_TXRXB_P -ETH_TXRXB_N
differential pair ETH_TXRXA: +ETH_TXRXA_P -ETH_TXRXA_N
differential pair DSI_D1: +DSI_D1_P -DSI_D1_N
differential pair DSI_D0: +DSI_D0_P -DSI_D0_N
differential pair DSI_CLK0: +DSI_CLK0_P -DSI_CLK0_N
differential pair CSI_D3: +CSI_D3_P -CSI_D3_N
differential pair CSI_D2: +CSI_D2_P -CSI_D2_N
differential pair CSI_D1: +CSI_D1_P -CSI_D1_N
differential pair CSI_D0: +CSI_D0_P -CSI_D0_N
differential pair CSI_CLK0: +CSI_CLK0_P -CSI_CLK0_N
differential pair CLK1: +CLK1_P -CLK1_N
differential pair CSID2: +CSID2_P -CSID2_N
differential pair CSID3: +CSID3_P -CSID3_N

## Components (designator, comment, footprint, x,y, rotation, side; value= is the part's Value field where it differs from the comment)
C1 "100uF" CAPMP3216X120N 92.5,21.625 r0 bottom
C2 "10uF" CAPC1005X55N 87.5,18.5 r90 bottom
C3 "1.0UF" CAPC1005X55N 89.5,24.5 r270 bottom
C4 "100nF" CAPC1005X55N 81.5,24.5 r180 bottom
C5 "100nF" CAPC1005X55N 75.5,24.5 r90 bottom
C6 "100nF" CAPC1005X55N 75.5,22.5 r270 bottom
C7 "100nF" CAPC1005X55N 75.5,18.5 r270 bottom
C8 "47µF" CAPMP6032X280N 88.125,41.5 r180 bottom
C9 "10uF" CAPC1005X55N 87.5,32.5 r0 bottom
C10 "100nF" CAPC1005X55N 87.5,34.5 r0 bottom
C11 "10uF" CAPC1005X55N 85.5,38.5 r180 bottom
C12 "10uF" CAPC1005X55N 75,13.25 r0 top
C13 "100nF" CAPC1005X55N 72.75,13.25 r180 top
C14 ".01uF" CAPC1005X55N 81.875,64.875 r90 bottom
C15 ".01uF" CAPC1005X55N 83.125,64.875 r90 bottom
C16 ".01uF" CAPC1005X55N 85.875,64.875 r90 bottom
C17 ".01uF" CAPC1005X55N 87.125,64.875 r90 bottom
C18 "1.0UF" CAPC1005X55N 20,62.25 r270 bottom
C19 "1.0UF" CAPC1005X55N 21.25,62.25 r90 bottom
C20 "1.0UF" CAPC1005X55N 37.375,62 r90 bottom
C21 "1.0UF" CAPC1005X55N 34.875,62 r270 bottom
C22 "1.0UF" CAPC1005X55N 20.375,55.875 r0 bottom
C23 "1.0UF" CAPC1005X55N 34.625,55 r270 bottom
C24 "1.0UF" CAPC1005X55N 21.875,55.125 r90 bottom
C25 "1.0UF" CAPC1005X55N 35.75,55 r270 bottom
C26 "1.0UF" CAPC1005X55N 22.5,62.25 r90 bottom
C27 "1.0UF" CAPC1005X55N 36.125,62 r270 bottom
C28 "22pF" CAPC1005X55N 27.125,41 r270 top
C29 "100nF" CAPC1005X55N 5.5,21.5 r270 top
C30 "22pF" CAPC1005X55N 32.5,40.375 r270 top
C31 "100nF" CAPC1005X55N 57.5,52.5 r270 bottom
C32 "100nF" CAPC1005X55N 55.5,52.5 r270 bottom
C33 "100nF" CAPC1005X55N 17.25,2 r90 bottom
C34 "100uF" CAPMP3216X120N 49.75,18.5 r180 bottom
C35 "100uF" CAPMP3216X120N 48.5,37 r180 bottom
C36 "100uF" CAPMP3216X120N 56.5,50.5 r180 bottom
C37 "100nF" CAPC1005X55N 51.5,44.5 r0 bottom
C38 "100nF" CAPC1005X55N 50.625,16.125 r90 bottom
C39 "100nF" CAPC1005X55N 49.5,38.5 r0 bottom
C40 "4.7uF" CAPC2013X135N 48.5,42.5 r0 bottom
C41 "100nF" CAPC1005X55N 51.5,42.5 r0 bottom
C42 "10uF" CAPC1005X55N 25.375,36.625 r0 top
C43 "100nF" CAPC1005X55N 27,29.125 r90 top
C44 "100nF" CAPC1005X55N 27.125,38.125 r270 top
C45 "100nF" CAPC1005X55N 25.375,35.5 r0 top
C46 "100nF" CAPC1005X55N 29.75,26.875 r90 top
C47 "100nF" CAPC1005X55N 34.125,38 r180 top
C48 "100nF" CAPC1005X55N 38.25,34.5 r180 top
C49 "10uF" CAPC1005X55N 36.375,26.875 r90 bottom
C50 "100nF" CAPC1005X55N 28.625,26.875 r90 top
C51 "100nF" CAPC1005X55N 31.5,26.875 r90 top
C52 "100nF" CAPC1005X55N 34.625,26.875 r90 top
C53 "100nF" CAPC1005X55N 37.5,29.625 r180 top
C54 "100nF" CAPC1005X55N 37.875,32 r180 top
C55 "100nF" CAPC1005X55N 36.75,38 r180 top
C56 "10uF" CAPC1005X55N 36.75,36.875 r180 top
C57 "10uF" CAPC1005X55N 25.375,30.125 r0 bottom
C58 "100nF" CAPC1005X55N 25.375,31.25 r0 top
C59 "100nF" CAPC1005X55N 25.375,34 r0 top
C60 "10uF" CAPC1005X55N 34,41.25 r180 top
C61 "100nF" CAPC1005X55N 34,40.25 r180 top
C62 "1.0UF" CAPC1005X55N 43.125,21.375 r180 bottom
C63 "33pF" CAPC1005X55N 29.5,40.625 r270 bottom
C64 "33pF" CAPC1005X55N 34.5,40.25 r90 bottom
C65 "1.0UF" CAPC1005X55N 25.125,20.25 r0 bottom
C66 "100nF" CAPC1005X55N 39.375,24 r270 bottom
C67 "10uF" CAPC1005X55N 38.25,23.75 r270 bottom
C68 "100nF" CAPC1005X55N 25.125,18.75 r180 bottom
C69 "10uF" CAPC1005X55N 27.625,18.75 r180 bottom
C70 "100nF" CAPC1005X55N 27.5,20.25 r180 bottom
C71 "10uF" CAPC1005X55N 28.875,17.625 r270 top
C72 "10uF" CAPC1005X55N 27.125,38.125 r270 bottom
C73 "100nF" CAPC1005X55N 30.625,26.875 r90 bottom
C74 "100nF" CAPC1005X55N 34.625,26.875 r90 bottom
C75 "100nF" CAPC1005X55N 37.875,32.5 r180 bottom
C76 "100nF" CAPC1005X55N 36.75,37 r180 bottom
C77 "100nF" CAPC1005X55N 25.375,32.375 r0 bottom
C78 "100nF" CAPC1005X55N 31.75,26.875 r90 bottom
C79 "100nF" CAPC1005X55N 34.125,38 r180 bottom
C80 "4.7uF" CAPC2013X135N 54.25,4.75 r0 bottom
C81 "100nF" CAPC1005X55N 57.875,5.25 r0 bottom
C82 "100nF" CAPC1005X55N 57.5,10.625 r0 top
C83 "100nF" CAPC1005X55N 48.25,4.875 r90 bottom
C84 "100nF" CAPC1005X55N 57.5,16.5 r0 bottom
C85 "100nF" CAPC1005X55N 49.375,16.125 r270 bottom
C86 "100nF" CAPC1005X55N 48.375,11.125 r180 top
C87 "1.0UF" CAPC1005X55N 71.5,20.625 r270 bottom
C88 "1.0UF" CAPC1005X55N 70.375,20.625 r270 bottom
C89 "100nF" CAPC1005X55N 65.5,24.5 r0 bottom
C90 "100nF" CAPC1005X55N 72.625,20.625 r90 bottom
C91 "1.0UF" CAPC1005X55N 68.125,20.625 r90 bottom
C92 "1.0UF" CAPC1005X55N 67,20.625 r90 bottom
C93 "1.0UF" CAPC1005X55N 65.875,20.625 r90 bottom
C94 "1.0UF" CAPC1005X55N 65.875,22.5 r270 bottom
C95 "100nF" CAPC1005X55N 65.5,26.5 r0 bottom
C96 "100nF" CAPC1005X55N 76.625,29.875 r270 bottom
C97 "100nF" CAPC1005X55N 73.5,26.5 r270 bottom
C98 "10uF" CAPC1005X55N 75.5,26.5 r270 bottom
C99 "100nF" CAPC1005X55N 85.5,60.5 r90 bottom
C100 "100nF" CAPC1005X55N 85.5,54.5 r180 bottom
C101 "100nF" CAPC1005X55N 18.25,52.625 r0 top
D1 "597-3301-507F" LEDM3020X130N 80.75,12.625 r180 top
D2 "BZX84C5V1-7-F" SOT95P240X110_AXK-3N 84.5,27.375 r0 bottom
D3 "BAT54_D87Z" SOT95P240X110_AXK-3N 54.125,12 r180 top
D4 "597-3301-507F" LEDM3020X130N 16.25,40.125 r0 top
D5 "597-3401-507F" LEDM3020X130N 11.625,40.125 r0 top
D6 "597-3021-507F" LEDM3020X130N 7,40.125 r0 top
D7 "ESD9B5.0ST5G" SODFL1006X43N12 67.625,13.25 r180 top
D8 "ESD9B5.0ST5G" SODFL1006X43N12 77.25,13.25 r0 top
D9 "ESD9B5.0ST5G" SODFL1006X43N12 69.875,13.25 r0 top
D10 "ESD9B5.0ST5G" SODFL1006X43N12 35.625,6.375 r270 bottom
FIDUCIAL1 "40mil FID" fiducial_40mil_round 95.125,13.5 r90 bottom
FIDUCIAL2 "40mil FID" fiducial_40mil_round 5.875,7.875 r90 bottom
FIDUCIAL3 "40mil FID" fiducial_40mil_round 5.75,63.5 r90 bottom
FIDUCIAL4 "40mil FID" fiducial_40mil_round 5.75,63.5 r90 top
FIDUCIAL5 "40mil FID" fiducial_40mil_round 94.75,12.5 r90 top
FIDUCIAL6 "40mil FID" fiducial_40mil_round 5.875,7.875 r90 top
H1048 "Comment" MH_185_125_NP -7.5,-4 r0 top
H1049 "Comment" MH_185_125_NP -7.5,72 r0 top
H1050 "Comment" MH_185_125_NP 312.5,72 r0 top
H1051 "Comment" MH_185_125_NP 312.5,-4 r0 top
H1052 "Comment" fiducial_40mil_round -7.5,64.5 r0 top
H1053 "Comment" fiducial_40mil_round -7.5,3.5 r0 top
H1054 "Comment" fiducial_40mil_round 312.5,3.5 r0 top
H1055 "Comment" fiducial_40mil_round 312.5,64.5 r0 top
J1 "CSCD443CCS011B00G" conn_CSCD443CCS011B00G 88,12 r90 top locked
J2 "1x2P" MOLEX_53047-0210 97.875,10.625 r270 top locked
J3 "1x3P" MOLEX_53047-0310 6,13.375 r90 top locked
J4 "1x2" FCI_68002-102HLF 15.125,47 r270 top locked
J5 "1x2" FCI_68002-102HLF 17.625,47 r270 top locked
J6 "70543-0001" CONN_70543-0001 73.875,67.875 r180 top locked
J7 "500873-0806" MOLEX_500873-0806 72.5,5.25 r0 bottom locked
J8 "5607-5102-SH" 3M_5607-5102-SH 81.25,70.5 r180 top locked
J9 "1x3P" MOLEX_53047-0310 6,49.875 r90 top locked
J10 "FTSH-105-01-F-DV" SAMTEC_FTSH-105-01-F-DV 11.75,53.125 r0 top locked
J11 "FTSH-105-01-F-DV" SAMTEC_FTSH-105-01-F-DV 11.75,60.125 r0 top locked
J12 "PCIe Minicard" FOXCONN_AS0B221-S68Q-7H 58.5,46.5 r270 bottom locked
J13 "RJ45" BELFUSE_61001-F 11,8 r0 top locked
J14 "78727-0001" MOLEX_78727-0001 72.5,50.125 r270 bottom locked
J15 "KUSBX-AS2N" KYCON_KUSBX-AS2N 30.5,13 r0 top locked
J16 "KMMX-ABSMT5SG-30TR" KYCON_KMMX-ABSMT5 34.3,1.5 r180 bottom locked
J17 "1x20P" omron_xf2m-2015-1a 44.5,68.75 r180 top locked
J18 "1x20P" omron_xf2m-2015-1a 61.25,68.75 r0 bottom locked
J19 "DF14A-20P-1.25H(25)" HIROSE_DF14A-20P-1.25H 21.75,67.75 r0 top locked
J20 "1x24P" OMRON_XF2M-2415-1A 60.25,68.75 r180 top locked
J21 "1x40" OMRON_XF2M-4015-1A 41.5,68.75 r0 bottom locked
J22 "3.5mm AUDIO" CUI_SJ1-3515-SMT 73.45,6.05 r90 top locked
J23 "1x10" SAMTEC_MMS-110-01-L-SV 21.072,50.758 r270 top locked
J24 "1x10" SAMTEC_MMS-110-01-L-SV 43.072,50.758 r270 top locked
J25 "1x3P" MOLEX_53047-0310 6,56.125 r90 top locked
J26 "1x8P" MOLEX_53047-0810 63.625,11.375 r270 top locked
J27 "1x6P" MOLEX_53047-0610#1 97.875,62.625 r270 top locked
J28 "1x6P" MOLEX_53047-0610#1 97.875,52.125 r270 top locked
J29 "1x14P" MOLEX_53047-1410 2.125,47.375 r90 top locked
J30 "1x14P" MOLEX_53047-1410 2.125,8.375 r90 top locked
J31 "1x14P" MOLEX_53047-1410 2.125,27.875 r90 top locked
J32 "1x6P" MOLEX_53047-0610#2 6,27.875 r90 top locked
J33 "1x14P" MOLEX_53047-1410 97.875,31.125 r270 top locked
J34 "1x6P" MOLEX_53047-0610#1 97.875,41.625 r270 top locked
L1 "IDCP1813ER4R7M" IND_SDR0403_4.5X4 91.5,36.5 r180 bottom
L2 "120" INDC1005X60N 25.375,37.75 r0 top
L3 "120" INDC1005X60N 36.25,26.875 r270 top
L4 "120" INDC1005X60N 36.75,39.125 r0 top
L5 "120" INDC1005X60N 34,42.5 r180 top
L6 "220" INDC2013X110N 32.5,16.625 r90 top
L7 "220" INDC2013X110N 30.5,16.625 r90 top
L8 "744231121" FIL_DLW21H 37.125,35.625 r0 bottom
L9 "220" INDC2013X110N 36.25,16.625 r90 top
L10 "744231121" FIL_DLW21H 34.375,16.375 r90 top
L11 "744231121" FIL_DLW21H 37.125,33.875 r0 bottom
L12 "220" INDC2013X110N 40.25,17.875 r270 top
L13 "220" INDC2013X110N 38.25,16.625 r270 top
L14 "744231121" FIL_DLW21H 38.375,31.125 r0 bottom
L15 "220" INDC2013X110N 27.25,17.625 r270 top
L16 "744231121" FIL_DLW21H 37.625,29.25 r0 bottom
L17 "220" INDC2013X110N 25.5,39 r90 bottom
L18 "120" INDC1005X60N 71.5,18.625 r270 bottom
L19 "120" INDC1005X60N 69.25,18.625 r270 bottom
L20 "120" INDC1005X60N 68.125,18.625 r90 bottom
L21 "120" INDC1005X60N 67,18.625 r90 bottom
L22 "120" INDC1005X60N 65.875,18.625 r90 bottom
L23 "120" INDC1005X60N 64.75,18.625 r90 bottom
L24 "120" INDC1005X60N 73.5,28.5 r90 bottom
L25 "120" INDC1005X60N 73.5,24.5 r270 bottom
L26 "220" INDC2013X110N 77.125,27.25 r270 bottom
L27 "220" INDC2013X110N 75.125,29.125 r270 bottom
L28 "220" INDC2013X110N 17.875,50.75 r180 top
P1 "KDMIX-NS1-NS-B" KYCON_KDMIX 52.375,8.5 r0 top locked
Q1 "MMBT3906LT1G" SOT95P240X110-3N 84.5,21.25 r0 bottom
Q2 "2N7002T" SOTFL50P160X80_GSD-3N 42.125,18.75 r0 bottom
R1 "49.9" RESC1005X40N 47.5,50.5 r180 bottom
R2 "49.9" RESC1005X40N 49.5,52.5 r0 bottom
R3 "49.9" RESC1005X40N 47.5,52.375 r180 bottom
R4 "0" RESC1005X40N 51.5,56.5 r270 bottom
R5 "0" RESC1005X40N 57.5,56.5 r0 bottom
R6 "0" RESC1005X40N 87.5,24.5 r90 bottom
R7 "10.0K" RESC1005X40N 13.75,51.875 r0 bottom
R8 "100" RESC1005X40N 92,19.25 r180 bottom
R9 "1.0K" RESC1005X40N 81.5,22.5 r90 bottom
R10 "1.0K" RESC1005X40N 81.5,18.5 r270 bottom
R11 "2.7k" RESC1005X40N 85.5,24.5 r0 bottom
R12 "220" RESC1005X40N 89.5,18.5 r90 bottom
R13 "10.0K" RESC1005X40N 83.5,24.5 r270 bottom
R14 "470K" RESC1005X40N 83.5,18.5 r90 bottom
R15 "316K" RESC1609X55N 79.5,27.5 r270 bottom
R16 "1.0K" RESC1005X40N 85.5,30.5 r0 bottom
R17 "1.0K" RESC1005X40N 87.5,30.5 r180 bottom
R18 "1.0K" RESC1005X40N 93.5,30.5 r180 bottom
R19 "1.0K" RESC1005X40N 83.375,30.5 r180 bottom
R20 "0" RESC1005X40N 87.5,38.5 r0 bottom
R21 "0" RESC1005X40N 89.5,32.5 r0 bottom
R22 "1.0K" RESC1005X40N 91.5,32.5 r180 bottom
R23 "1M_1%" RESC1005X40N 85.5,34.5 r0 bottom
R24 "0" RESC1005X40N 81.5,56.5 r0 bottom
R25 "0" RESC1005X40N 81.5,52.5 r0 bottom
R26 "22.1K" RESC1005X40N 83.625,38.5 r270 bottom
R27 "316K" RESC1609X55N 83.75,35.125 r90 bottom
R28 "10.0K" RESC1005X40N 81.5,54.5 r180 bottom
R29 "10.0K" RESC1005X40N 81.5,50.5 r180 bottom
R30 "22.1K" RESC1005X40N 85.5,44.5 r0 bottom
R31 "10.0K" RESC1005X40N 91.5,46.5 r90 bottom
R32 "10.0K" RESC1005X40N 93.5,42.5 r180 bottom
R33 "10.0K" RESC1005X40N 87.5,46.5 r90 bottom
R34 "10.0K" RESC1005X40N 93.5,40.5 r180 bottom
R35 "100" RESC1005X40N 89.5,46.5 r90 bottom
R36 "10.0K" RESC1005X40N 81.5,58.5 r0 bottom
R37 "4.7K" RESC1005X40N 85.5,48.5 r90 bottom
R38 "220" RESC1005X40N 17.375,10.25 r90 bottom
R39 "1M_1%" RESC1005X40N 29,38 r180 top
R40 "4.7K" RESC1005X40N 51.5,22.5 r180 bottom
R41 "1.0K" RESC1005X40N 51.5,24.5 r270 bottom
R42 "49.9" RESC1005X40N 53.875,52.125 r0 bottom
R43 "49.9" RESC1005X40N 58.625,52.5 r270 bottom
R44 "0" RESC1005X40N 63.25,58.5 r270 bottom
R45 "220" RESC1005X40N 16.125,10.25 r90 bottom
R46 "100" RESC1005X40N 16.125,2 r270 bottom
R47 "0" RESC1005X40N 64.25,58.5 r270 bottom
R48 "100" RESC1005X40N 36.75,41.375 r180 top
R49 "12.1k" RESC1005X40N 25.375,38.875 r0 top
R50 "1.0K" RESC1005X40N 36.75,40.25 r180 top
R51 "0" RESC1005X40N 65,30.75 r180 bottom
R52 "0" RESC1005X40N 65,29.625 r180 bottom
R53 "10.0K" RESC1005X40N 16.125,8.125 r90 bottom
R54 "1.0K" RESC1005X40N 16.125,6 r270 bottom
R55 "10.0K" RESC1005X40N 17.375,8.125 r90 bottom
R56 "1.0K" RESC1005X40N 17.375,6 r270 bottom
R57 "1.0K" RESC1005X40N 55.5,16.5 r0 bottom
R58 "10.0K" RESC1005X40N 51.5,28.5 r180 bottom
R59 "1.0K" RESC1005X40N 49.5,26.5 r180 bottom
R60 "10.0K" RESC1005X40N 49.5,22.5 r0 bottom
R61 "10.0K" RESC1005X40N 49.5,20.5 r0 bottom
R62 "10.0K" RESC1005X40N 59.5,16.5 r270 bottom
R63 "10.0K" RESC1005X40N 51.5,20.5 r180 bottom
R64 "10.0K" RESC1005X40N 42.125,29.25 r180 top
R65 "10.0K" RESC1005X40N 24.49,27.2 r90 top
R66 "10.0K" RESC1005X40N 25.76,27.2 r270 top
R67 "1M_1%" RESC1005X40N 32.25,38 r0 bottom
R68 "47K" RESC1005X40N 25.375,36.875 r180 bottom
R69 "10.0K" RESC1005X40N 25.375,35.75 r0 bottom
R70 "12.1k" RESC1005X40N 36.75,38.125 r180 bottom
R71 "47K" RESC1005X40N 25.375,31.25 r0 bottom
R72 "10.0K" RESC1005X40N 41.375,21.375 r270 bottom
R73 "47K" RESC1005X40N 25.375,33.5 r0 bottom
R74 "47K" RESC1005X40N 25.375,34.625 r0 bottom
R75 "4.7K" RESC1005X40N 43.75,19.25 r270 bottom
R76 "10.0K" RESC1005X40N 11.125,65.125 r270 bottom
R77 "10.0K" RESC1005X40N 61.5,62.5 r0 bottom
R78 "10.0K" RESC1005X40N 49.25,63.875 r180 bottom
R79 "0" RESC1005X40N 61.5,56.5 r180 bottom
R80 "0" RESC1005X40N 61.5,54.5 r180 bottom
R81 "0" RESC1005X40N 57.5,60.5 r180 bottom
R82 "0" RESC1005X40N 57.5,62.5 r180 bottom
R83 "0" RESC1005X40N 59.5,54.5 r0 bottom
R84 "0" RESC1005X40N 59.5,56.5 r0 bottom
R85 "4.7K" RESC1005X40N 48.375,12.25 r180 top
R86 "27K" RESC1005X40N 51.375,11.125 r180 top
R87 "4.7K" RESC1005X40N 57.75,13.25 r0 top
R88 "47K" RESC1005X40N 50.875,4.875 r90 bottom
R89 "15.0k" RESC1005X40N 48.125,16.125 r270 bottom
R90 "47K" RESC1005X40N 49.375,4.875 r90 bottom
R91 "10.0K" RESC1005X40N 70.375,18.625 r90 bottom
R92 "10.0K" RESC1005X40N 72.625,18.625 r90 bottom
R93 "10.0K" RESC1005X40N 73.5,22.5 r180 bottom
R94 "2.2K" RESC1005X40N 64.75,20.625 r90 bottom
R95 "0" RESC1005X40N 51.5,32.5 r180 bottom
R96 "0" RESC1005X40N 51.5,46.5 r270 bottom
R97 "0" RESC1005X40N 51.5,34.5 r180 bottom
R98 "0" RESC1005X40N 47.5,48.5 r90 bottom
R99 "0" RESC1005X40N 47.5,28.375 r0 bottom
R100 "0" RESC1005X40N 53.5,50.5 r90 bottom
R101 "0" RESC1005X40N 49.5,30.5 r180 bottom
R102 "0" RESC1005X40N 49.5,48.5 r90 bottom
R103 "0" RESC1005X40N 49.5,32.5 r180 bottom
R104 "120" RESC1005X40N 91.5,56.5 r0 bottom
R105 "0" RESC1005X40N 51.5,48.5 r90 bottom
R106 "0" RESC1005X40N 49.5,34.5 r180 bottom
R107 "0" RESC1005X40N 49.5,44.5 r180 bottom
R108 "0" RESC1005X40N 47.5,34.375 r180 bottom
R109 "2.2K" RESC1005X40N 51.5,30.5 r180 bottom
R110 "2.2K" RESC1005X40N 49.5,50.5 r90 bottom
R111 "0" RESC1005X40N 49.5,46.5 r270 bottom
R112 "0" RESC1005X40N 47.5,32.5 r180 bottom
R113 "0" RESC1005X40N 51.5,50.5 r90 bottom
R114 "0" RESC1005X40N 47.5,30.625 r180 bottom
R115 "0" RESC1005X40N 47.5,46.5 r270 bottom
R116 "120" RESC1005X40N 93.5,56.5 r0 bottom
R117 "10.0K" RESC1005X40N 93.5,48.5 r0 bottom
R118 "10.0K" RESC1005X40N 5.75,42.125 r270 bottom
R119 "120" RESC1005X40N 15,40.125 r90 bottom
R120 "120" RESC1005X40N 10.375,40.125 r90 bottom
R121 "120" RESC1005X40N 5.75,40.125 r90 bottom
R122 "10.0K" RESC1005X40N 47.5,44.5 r0 bottom
R123 "0" RESC1005X40N 91.5,30.5 r0 bottom
R124 "0" RESC1005X40N 93.5,32.5 r180 bottom
SW1 "KSC221JLFS" SW_KSC221J 13.5,35.25 r90 top
SW2 "ADTSJW65RVTR" APEM_ADTSJW65 13.5,28.5 r0 top
U1 "module" MODULE_CCWMX6 70.5,39.5 r0 top locked
U2 "NLASB3157DFT2G" SOT65P210X110-6N 78.5,21.5 r270 bottom
U3 "FDMA510PZ" DFN200X200X80-6N 88.375,21.625 r180 bottom
U4 "NLASB3157DFT2G" SOT65P210X110-6N 78.5,18.5 r270 bottom
U5 "SMBJ5.0A-E3/5B" DIOM5436X244N 90.5,27.5 r180 bottom
U6 "NC7S00P5X" SOT65P210X110-5N 78.5,24.5 r270 bottom
U7 "LTC3125EDCB" SON45P300X200X80_175X145E-9AN 86.5,36.5 r0 bottom
U8 "SP3243" SOP65P780X200-28N 24.272,58.75 r90 top
U9 "SP3243" SOP65P780X200-28N 38.75,58.5 r90 top
U10 "KSZ9031RNXI" QFN50P700X700X100-49N 31.875,32.75 r0 top
U11 "SI2323DS-T1-E3" SOT95P240X110_GSD-3N 39.625,41.75 r180 top
U12 "MIC2026" SOIC127P600X175-8N 43.25,26.125 r0 bottom
U13 "USB2514BI-AEZG" QFN50P600X600X100-37AN 31.875,32.75 r180 bottom
U14 "MIC2026" SOIC127P600X175-8N 25.125,24.5 r0 bottom
U15 "SI2323DS-T1-E3" SOT95P240X110_GSD-3N 39.25,19.5 r180 bottom
U16 "CM2020-01" SOP50P640X120-38N 53.875,10.75 r90 bottom
U17 "SGTL5000" QFN50P500X500X100-33CN 69.5,26.5 r180 bottom
U18 "SN65HVD233DR" SOIC127P600X175-8N 90.625,60.375 r90 bottom
U19 "SN65HVD233DR" SOIC127P600X175-8N 90.5,52.5 r90 bottom
U20 "TPD4E001DRSR" SON95P300X300X80-7N 29.625,22.875 r0 bottom
U21 "TPD4E001DRSR" SON95P300X300X80-7N 43.25,26.25 r270 top
X1 "RH100-25.000-20-TR-50PPM" OSC210P320X250X90-4N 29.75,40.375 r0 top
X2 "24MHz" XTAL_C3E-3427 32,40.25 r180 bottom

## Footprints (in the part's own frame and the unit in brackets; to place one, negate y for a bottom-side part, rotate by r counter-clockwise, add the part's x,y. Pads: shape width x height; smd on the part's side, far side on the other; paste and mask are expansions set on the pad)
3M_5607-5102-SH [mil]
  rrect50% 42x58 hole 29: 1(0,0)
  oval 42x58 hole 29: 2(-50,39.37) 3(-100,39.37) 4(-150,0) 5(-200,39.37) 6(-250,39.37) 7(-300,0)
  round 86 hole 55: 8(105,20) 9(-405,20)
  body extent -481,-59 180,165, height 331
APEM_ADTSJW65 [mm]
  rect 2.3x1 smd: 1(-3.15,2) 2(3.15,2) 3(-3.15,-2) 4(3.15,-2)
  body extent -3.5,-3.1 3.5,3.1, height 6.35
BELFUSE_61001-F [mil]
  rect 60x60 hole 35: 1(0,350)
  round 60 hole 35: 2(50,250) 3(100,350) 4(150,250) 5(200,350) 6(250,250) 7(300,350) 8(350,250) 9(400,350) 10(450,250)
  round 66 hole 40: D1(-36,-160) D2(64,-160) D3(386,-160) D4(486,-160)
  round 125 hole 125 unplated: MNT1(0,0) MNT2(450,0)
  round 100 hole 63: SHLD1(-80,120) SHLD2(530,120)
  body extent -129,-425 579,425, height 610
CAPC1005X55N [mm]
  rect 0.6x0.62 smd: 1(-0.46,0) 2(0.46,0)
  body extent -0.5,-0.25 0.5,0.25, height 0.55
CAPC2013X135N [mm] "0805, 1.35mm max height"
  rect 1.05x1.4 smd: 1(-0.9,0) 2(0.9,0)
  body extent -1.1,-0.72 1.1,0.72, height 1.35
CAPMP3216X120N [mm]
  rect 1.75x1.3 smd: 1(-1.35,0) 2(1.35,0)
  body extent -1.7,-0.9 1.7,0.9, height 1.21
CAPMP6032X280N [mm]
  rect 2.35x2.25 smd: 1(-2.45,0) 2(2.45,0)
  body extent -3.15,-1.75 3.15,1.75, height 2.81
CONN_70543-0001 [mil]
  rect 74x74 hole 45: 1(0,0)
  round 74 hole 45: 2(100,0)
  body extent -95,-160 195,100, height 465
conn_CSCD443CCS011B00G [mil] "Bobbintron : CSCD443CCS011B00G"
  rect 65x150 hole 40 slot 126 at 90 deg: 1(0,0)
  rrect50% 65x150 / inner rect 65x150 / far side rrect50% 65x150 hole 40 slot 126 at 90 deg: 2(-260,0)
  rrect50% 150x65 / inner rect 150x65 / far side rrect50% 150x65 hole 40 slot 126 at 0 deg: 3(-120,-197.01)
  round 0 hole 93 unplated: 4(-409,0)
  body extent -571,-207 20,177, height 433
CUI_SJ1-3515-SMT [mm]
  rect 2.9x1.75 smd: 1(-3.25,5.75)
  rect 2.9x2.25 smd: 2(3.25,-5.75)
  rect 2.1x1.75 smd: 3(2.95,5.75)
  rect 2.4x2.25 smd: 4(-1.15,-5.75)
  rect 1.8x1.75 smd: 5(0.05,5.75)
  round 0 hole 1.6 unplated: MT1(-3.05,-0.125) MT2(2.95,-0.125)
  body extent -9.05,-6.12 5.95,5.88, height 5
DFN200X200X80-6N [mm]
  rect 0.4x0.47 smd: 1(-0.65,-0.91) 2(0,-0.91) 3(0.65,-0.91) 4(0.65,0.91) 5(0,0.91) 6(-0.65,0.91)
  rect 1x1 smd: 7(-0.3,0)
  rect 0.4x0.66 smd: 8(0.65,0)
  body extent -1,-1 1,1, height 0.8
DIOM5436X244N [mm]
  rect 2.2x2.15 smd: A(-2.2,0) K(2.2,0)
  body extent -2.8,-1.97 2.8,1.97, height 2.44
FCI_68002-102HLF [mil]
  rect 74x74 hole 45: 1(0,0)
  round 74 hole 45: 2(100,0)
  body extent -51,-46 149,49, height 330
fiducial_40mil_round [mil]
  round 40 smd paste-40 mask+20: 1(0,0)
  Top Layer pour cut-out: -40,0 -36.96,15.31 -28.28,28.28 -15.31,36.96 0,40 0,40 15.31,36.96 28.28,28.28 36.96,15.31 40,0 40,0 36.96,-15.31 28.28,-28.28 15.31,-36.96 0,-40 0,-40 -15.31,-36.96 -28.28,-28.28 -36.96,-15.31 -40,0
FIL_DLW21H [mm]
  rect 0.9x0.4 smd: 1(-0.85,-0.4) 2(0.85,-0.4) 3(0.85,0.4) 4(-0.85,0.4)
  body extent -1.1,-0.7 1.1,0.7, height 1
FOXCONN_AS0B221-S68Q-7H [mm]
  rect 0.55x2 smd: 1(0.7,-4.1) 2(1.1,4.1) 3(1.5,-4.1) 4(1.9,4.1) 5(2.3,-4.1) 6(2.7,4.1) 7(3.1,-4.1) 8(3.5,4.1) 9(3.9,-4.1) 10(4.3,4.1) 11(4.7,-4.1) 12(5.1,4.1) 13(5.5,-4.1) 14(5.9,4.1) 15(6.3,-4.1) 16(6.7,4.1) 17(10.3,-4.1) 18(10.7,4.1) 19(11.1,-4.1) 20(11.5,4.1) 21(11.9,-4.1) 22(12.3,4.1) 23(12.7,-4.1) 24(13.1,4.1) 25(13.5,-4.1) 26(13.9,4.1) 27(14.3,-4.1) 28(14.7,4.1) 29(15.1,-4.1) 30(15.5,4.1) 31(15.9,-4.1) 32(16.3,4.1) 33(16.7,-4.1) 34(17.1,4.1) 35(17.5,-4.1) 36(17.9,4.1) 37(18.3,-4.1) 38(18.7,4.1) 39(19.1,-4.1) 40(19.5,4.1) 41(19.9,-4.1) 42(20.3,4.1) 43(20.7,-4.1) 44(21.1,4.1) 45(21.5,-4.1) 46(21.9,4.1) 47(22.3,-4.1) 48(22.7,4.1) 49(23.1,-4.1) 50(23.5,4.1) 51(23.9,-4.1) 52(24.3,4.1)
  round 0 hole 1.6 unplated: H1(0,0)
  round 0 hole 1.1 unplated: H2(25,0)
  rect 2.3x3.2 smd: MT1(-2.15,-3.5) MT2(27.15,-3.5)
  body extent -2.4,-4.75 27.4,4.75, height 6.8
HIROSE_DF14A-20P-1.25H [mm]
  rect 0.7x1.8 smd: 1(11.875,-2.55) 2(10.625,-2.55) 3(9.375,-2.55) 4(8.125,-2.55) 5(6.875,-2.55) 6(5.625,-2.55) 7(4.375,-2.55) 8(3.125,-2.55) 9(1.875,-2.55) 10(0.625,-2.55) 11(-0.625,-2.55) 12(-1.875,-2.55) 13(-3.125,-2.55) 14(-4.375,-2.55) 15(-5.625,-2.55) 16(-6.875,-2.55) 17(-8.125,-2.55) 18(-9.375,-2.55) 19(-10.625,-2.55) 20(-11.875,-2.55)
  rect 2x2.6 smd: MT1(14.275,2.55) MT21(-14.275,2.55)
  body extent -14.97,-3.02 14.97,3.67, height 2.49
IND_SDR0403_4.5X4 [mm]
  round 0.25 smd paste-0.4 mask-0.4: 1(0,1.6) 2(0,-1.6)
  Top Layer region: -2.25,0.8 -2.25,2.05 -2.212,2.241 -2.104,2.404 -1.941,2.512 -1.75,2.55 -1.75,2.55 1.75,2.55 1.941,2.512 2.104,2.404 2.212,2.241 2.25,2.05 2.25,2.05 2.25,0.8
  Top Layer region: 2.25,-0.8 2.25,-2.05 2.212,-2.241 2.104,-2.404 1.941,-2.512 1.75,-2.55 1.75,-2.55 -1.75,-2.55 -1.941,-2.512 -2.104,-2.404 -2.212,-2.241 -2.25,-2.05 -2.25,-2.05 -2.25,-0.8
  silkscreen extent -2.16,-0.51 2.16,0.51, body extent -2.38,-2.15 2.38,2.15
INDC1005X60N [mm]
  rect 0.59x0.72 smd: 1(-0.48,0) 2(0.48,0)
  body extent -0.55,-0.35 0.55,0.35, height 0.6
INDC2013X110N [mm]
  rect 1.2x1.45 smd: 1(-0.85,0) 2(0.85,0)
  body extent -1.1,-0.72 1.1,0.72, height 1.1
KYCON_KDMIX [mm]
  rect 0.28x2.7 smd: 1(4.5,0) 2(4,0) 3(3.5,0) 4(3,0) 5(2.5,0) 6(2,0) 7(1.5,0) 8(1,0) 9(0.5,0) 10(0,0) 11(-0.5,0) 12(-1,0) 13(-1.5,0) 14(-2,0) 15(-2.5,0) 16(-3,0) 17(-3.5,0) 18(-4,0) 19(-4.5,0)
  round 2 hole 1.27 unplated: H1(4.5,-6.3) H2(-4.5,-6.3)
  rect 2.5x3.2 smd: M1(8.05,-0.85) M2(-8.05,-0.85)
  rect 2.5x2.5 smd: M3(8.05,-6.81) M4(-8.05,-6.81)
  silkscreen extent -7.5,-10.17 7.5,1.29, body extent -8.58,-11.47 8.62,0.65, height 6.11
KYCON_KMMX-ABSMT5 [mm]
  rect 0.4x0.7 smd mask+0.058: 1(-1.3,3)
  rect 0.4x1.4 smd: 2(-0.65,2.65) 3(0,2.65) 4(0.65,2.65)
  rect 0.4x0.65 smd mask+0.058: 5(1.3,3.025)
  rect 2.3x1.9 smd: 6(-3.75,0) 9(3.75,0)
  rect 1.8x1.9 smd: 7(-1.15,0) 8(1.15,0)
  round 0 hole 0.813 unplated: 10(-1.9,2.18) 11(1.9,2.18)
  Top Layer region: -1.1,2.7 -1.1,1.95 -1.275,1.95 -1.275,2.18 -1.278,2.235 -1.28,2.258 -1.282,2.278 -1.285,2.29 -1.288,2.305 -1.29,2.315 -1.292,2.328 -1.3,2.355 -1.308,2.378 -1.315,2.4 -1.32,2.412 -1.335,2.448 -1.34,2.458 -1.342,2.462 -1.345,2.468 -1.358,2.49 -1.372,2.515 -1.388,2.538 -1.4,2.555 -1.418,2.578 -1.435,2.598 -1.482,2.645 -1.5,2.66 -1.5,2.7
  Top Layer region: 1.1,2.7 1.1,1.95 1.275,1.95 1.275,2.18 1.278,2.235 1.28,2.258 1.282,2.278 1.285,2.29 1.288,2.305 1.29,2.315 1.292,2.328 1.3,2.355 1.308,2.378 1.315,2.4 1.32,2.412 1.335,2.448 1.34,2.458 1.342,2.462 1.345,2.468 1.358,2.49 1.372,2.515 1.388,2.538 1.4,2.555 1.418,2.578 1.435,2.598 1.482,2.645 1.5,2.66 1.5,2.7
  silkscreen extent -2.49,3.26 -2.26,3.49, body extent -4.4,-2.72 4.4,2.88, height 2.78
KYCON_KUSBX-AS2N [mil]
  rect 60x60 hole 35: A1(0,0)
  round 60 hole 35: A2(98.43,0) A3(177.17,0) A4(275.59,0) B1(0,-103.15) B2(98.43,-103.15) B3(177.17,-103.15) B4(275.59,-103.15)
  round 150 hole 93: SH1(-120.87,-209.84) SH2(-120.87,13.78) SH3(396.46,-209.84) SH4(396.46,13.78)
  body extent -171,-633 446,56, height 634
LEDM3020X130N [mm]
  rect 1.3x2.2 smd: A(-1.3,0) K(1.3,0)
  body extent -1.6,-1.1 1.6,1.1, height 1.5
MH_185_125_NP [mm]
  round 3.175 hole 3.175 unplated: 1(0,0)
  Keep-Out Layer circle w0.102: c0,0 r2.349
